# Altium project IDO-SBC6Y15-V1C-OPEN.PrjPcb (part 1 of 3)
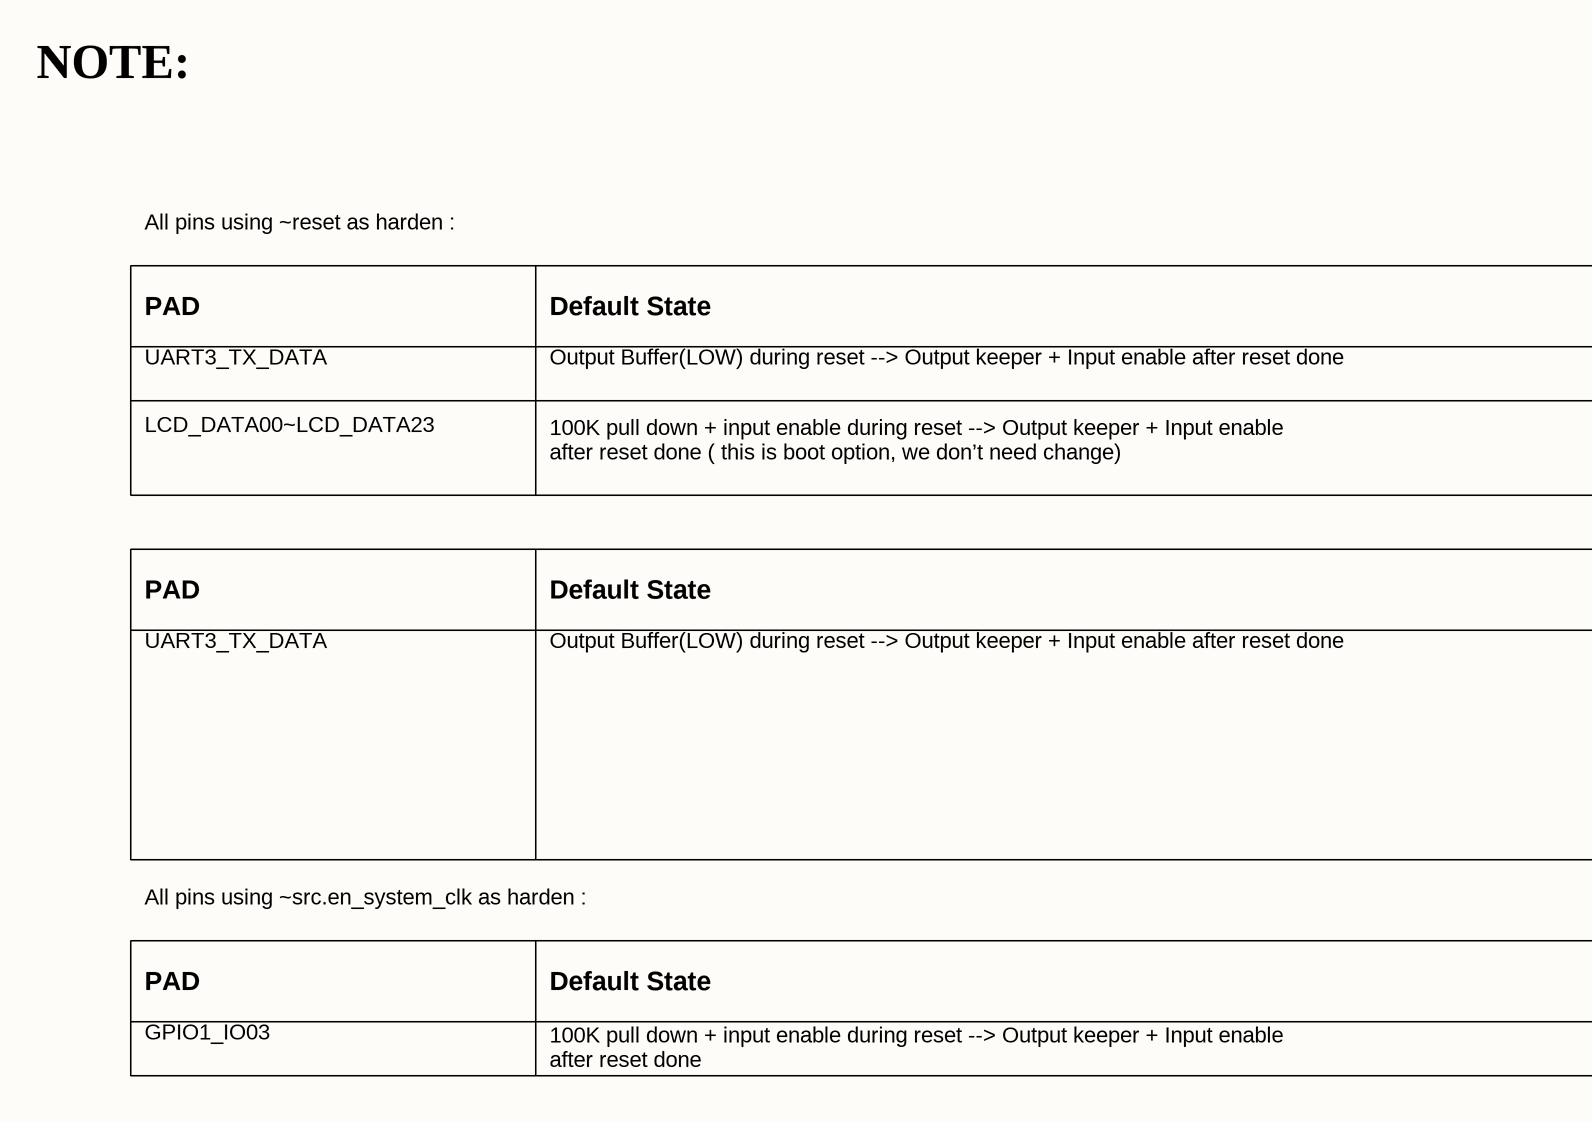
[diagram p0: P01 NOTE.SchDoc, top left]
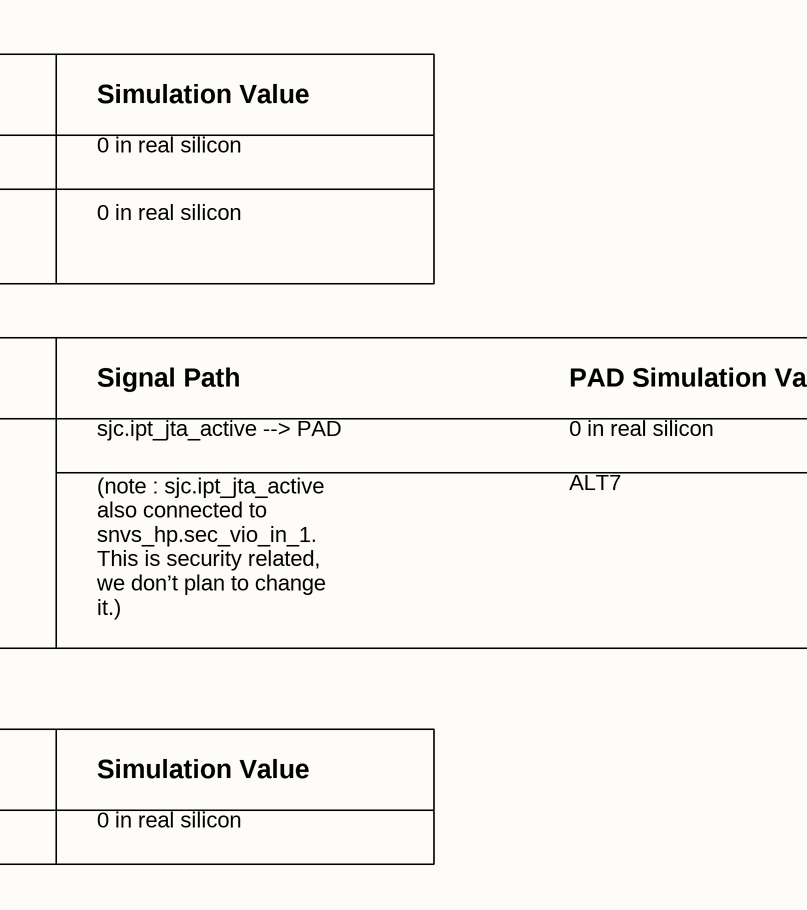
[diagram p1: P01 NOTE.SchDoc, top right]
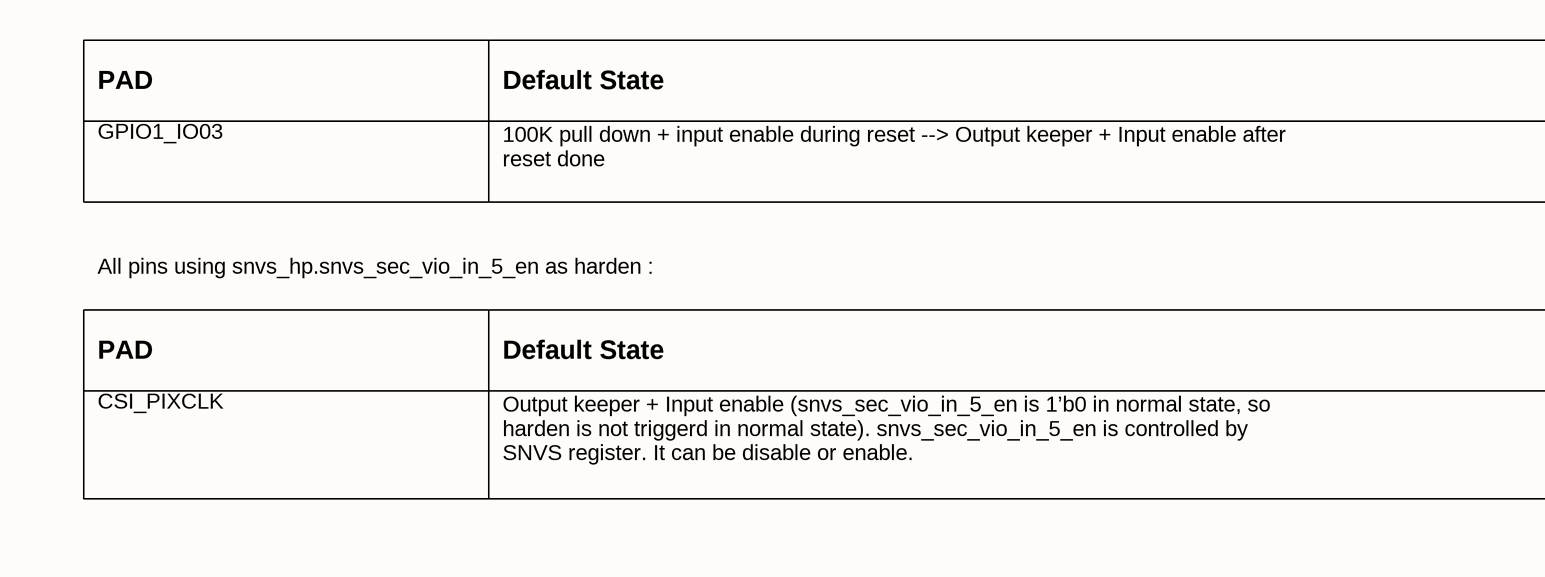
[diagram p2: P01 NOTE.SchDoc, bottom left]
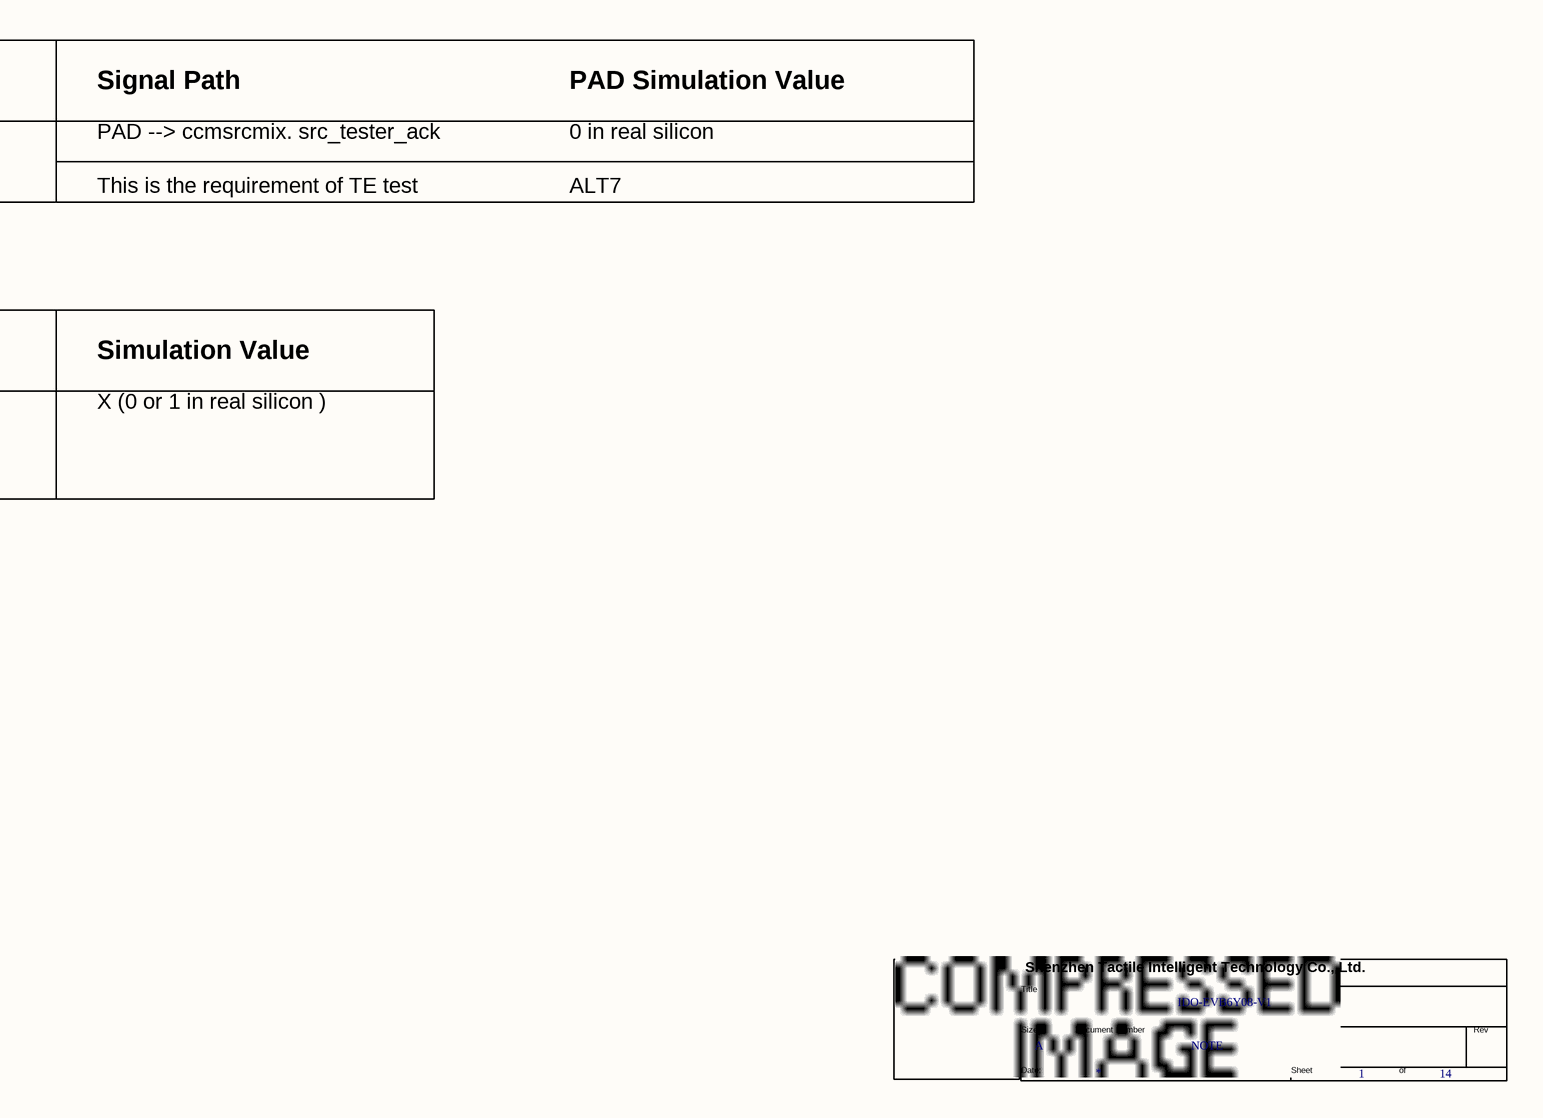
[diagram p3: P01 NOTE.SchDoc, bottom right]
12 sheets, 461 parts. Net scope: global (net labels, ports and power ports of the same name join across sheets).
Sheets:
  P01 NOTE.SchDoc
  P02 IOMUX.SchDoc
  P03 POWER TREE.SchDoc
  P04 BLOCK.SchDoc
  P05 POWER_SUPPLY_LED.SchDoc
  P06 SOM6ULX.SchDoc
  P07 SD_RTC.SchDoc
  P08 USB.SchDoc
  P09 ETHERNET.SchDoc
  P10 UART_Debug.SchDoc
  P12 EXPAND.SchDoc
  P11 4G_WIFI.SchDoc

## Sheet P01 NOTE.SchDoc
size 594 x 420 mm

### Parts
(Parts that share a designator on the sheet are numbered #1, #2 ... from top to bottom, then left to right.)
*#1  Doc: NOTE  Title: IDO-EVB6Y08-V1  Page Size: A  Page Number: 1  Page Count: 14  (hidden comment: TitleBlock1)  (graphical)

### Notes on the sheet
- NOTE:
- All pins using ~reset as harden :
- PAD
- Default State
- Simulation Value
- UART3_TX_DATA
- Output Buffer(LOW) during reset --> Output keeper + Input enable after reset done
- 0 in real silicon
- LCD_DATA00~LCD_DATA23
- 100K pull down + input enable during reset --> Output keeper + Input enable
  after reset done ( this is boot option, we don’t need change)
- sjc.ipt_jta_active --> PAD
- Signal Path
- PAD Simulation Value
- (note : sjc.ipt_jta_active
  also connected to
  snvs_hp.sec_vio_in_1.
  This is security related,
  we don’t plan to change
  it.)
- ALT7
- All pins using ~src.en_system_clk as harden :
- GPIO1_IO03
- 100K pull down + input enable during reset --> Output keeper + Input enable
  after reset done
- 100K pull down + input enable during reset --> Output keeper + Input enable after
  reset done
- PAD --> ccmsrcmix. src_tester_ack
- This is the requirement of TE test
- All pins using snvs_hp.snvs_sec_vio_in_5_en as harden :
- CSI_PIXCLK
- Output keeper + Input enable (snvs_sec_vio_in_5_en is 1’b0 in normal state, so
  harden is not triggerd in normal state). snvs_sec_vio_in_5_en is controlled by
  SNVS register. It can be disable or enable.
- X (0 or 1 in real silicon )

## Sheet P02 IOMUX.SchDoc
size 594 x 420 mm
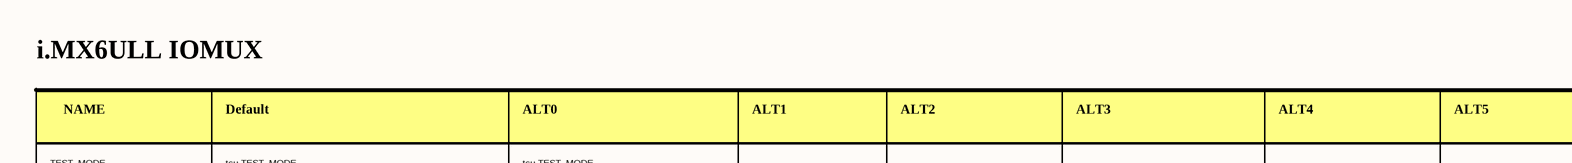
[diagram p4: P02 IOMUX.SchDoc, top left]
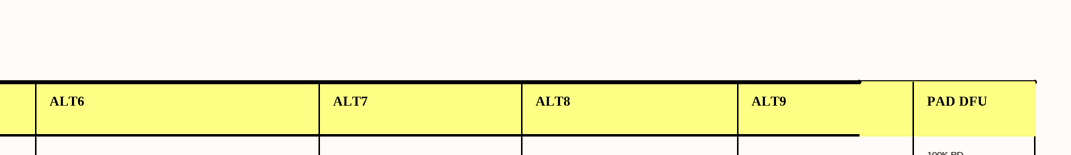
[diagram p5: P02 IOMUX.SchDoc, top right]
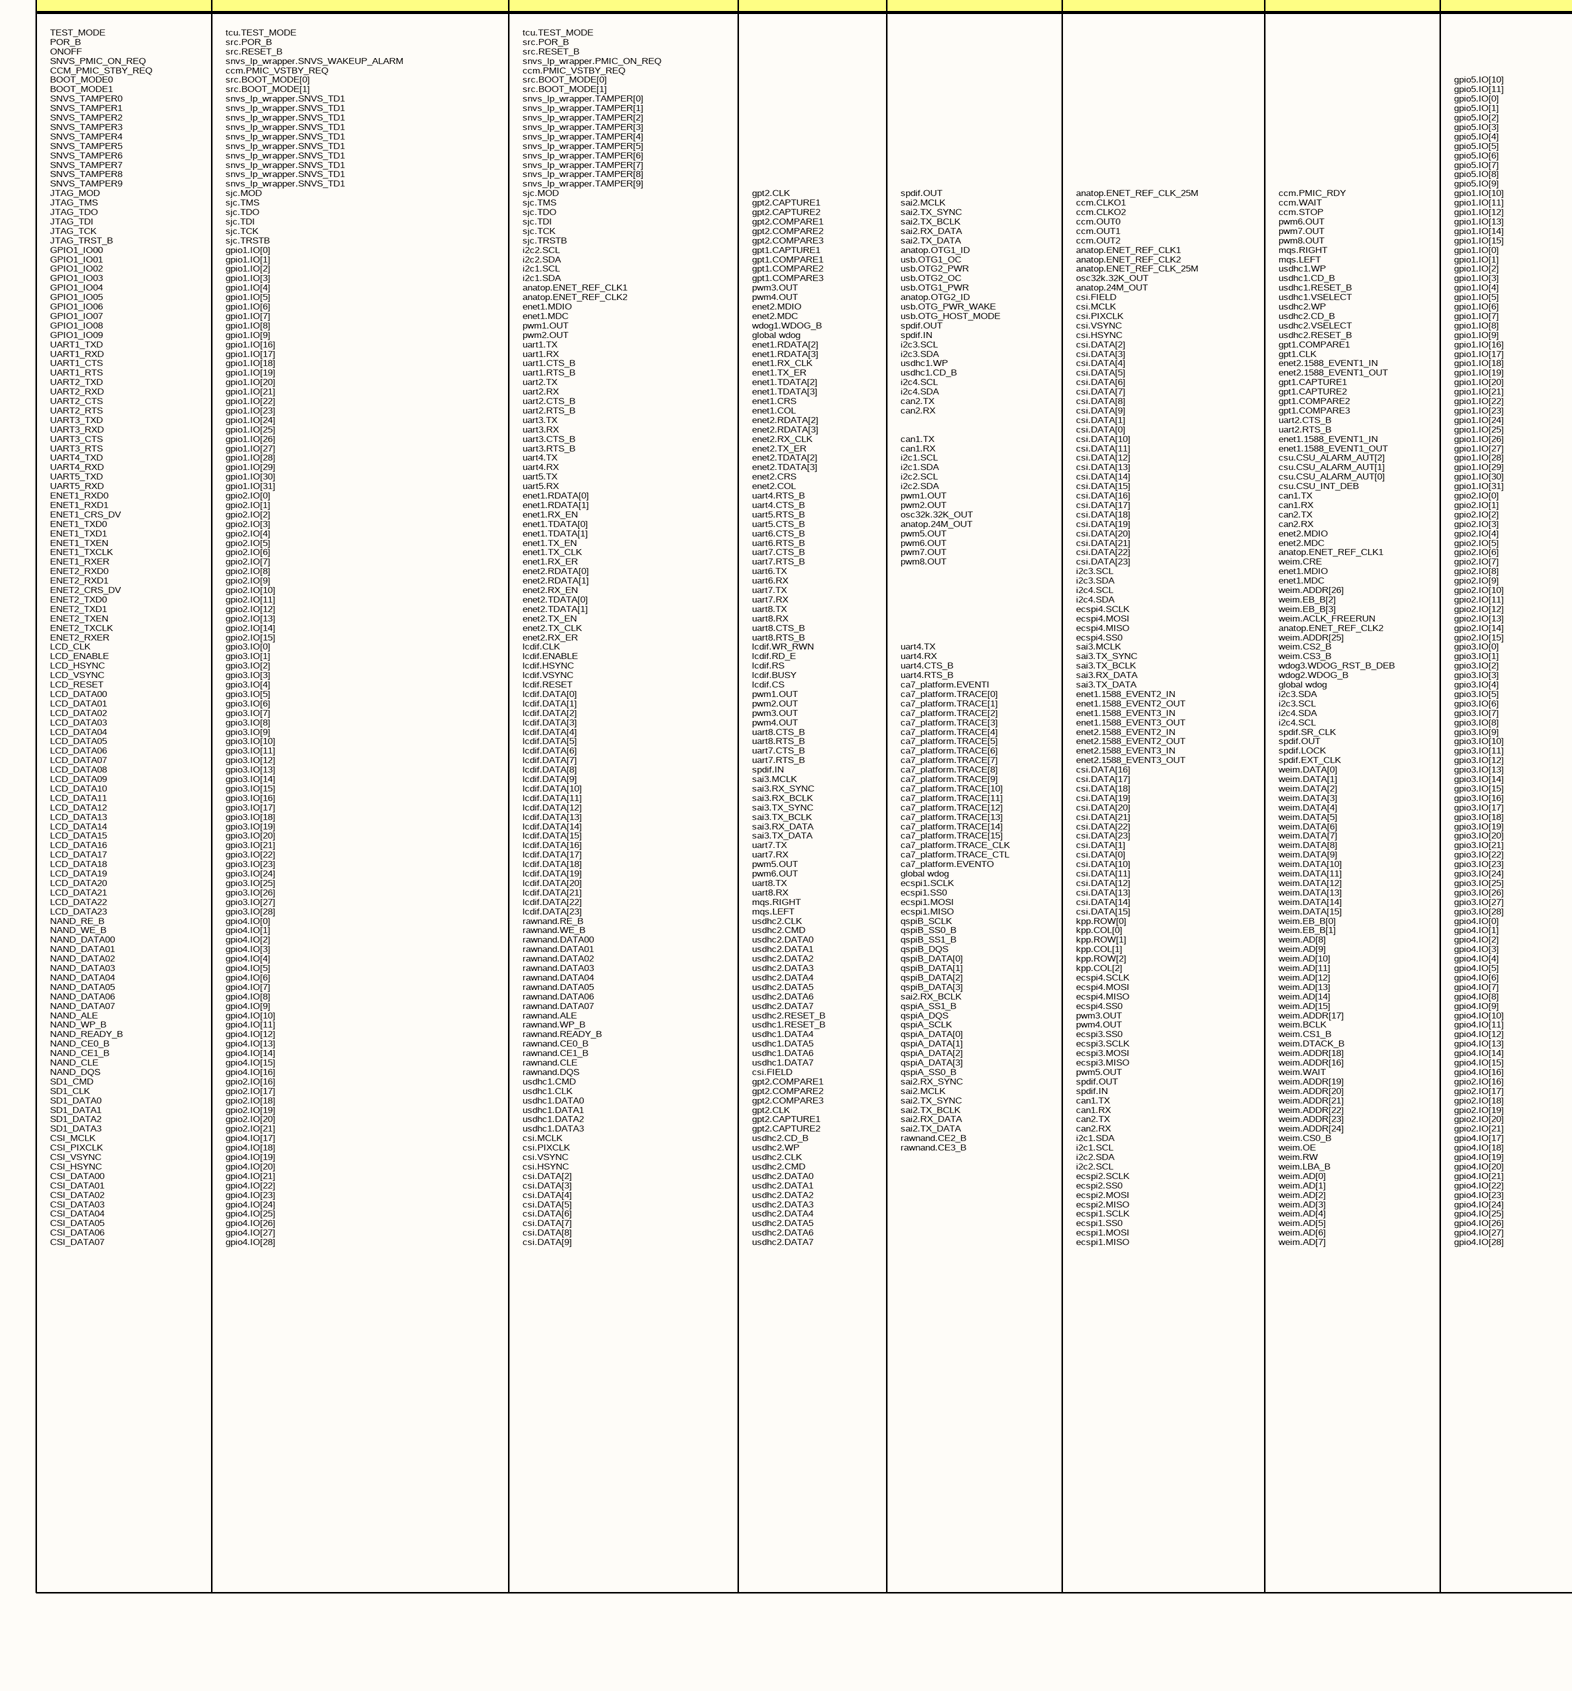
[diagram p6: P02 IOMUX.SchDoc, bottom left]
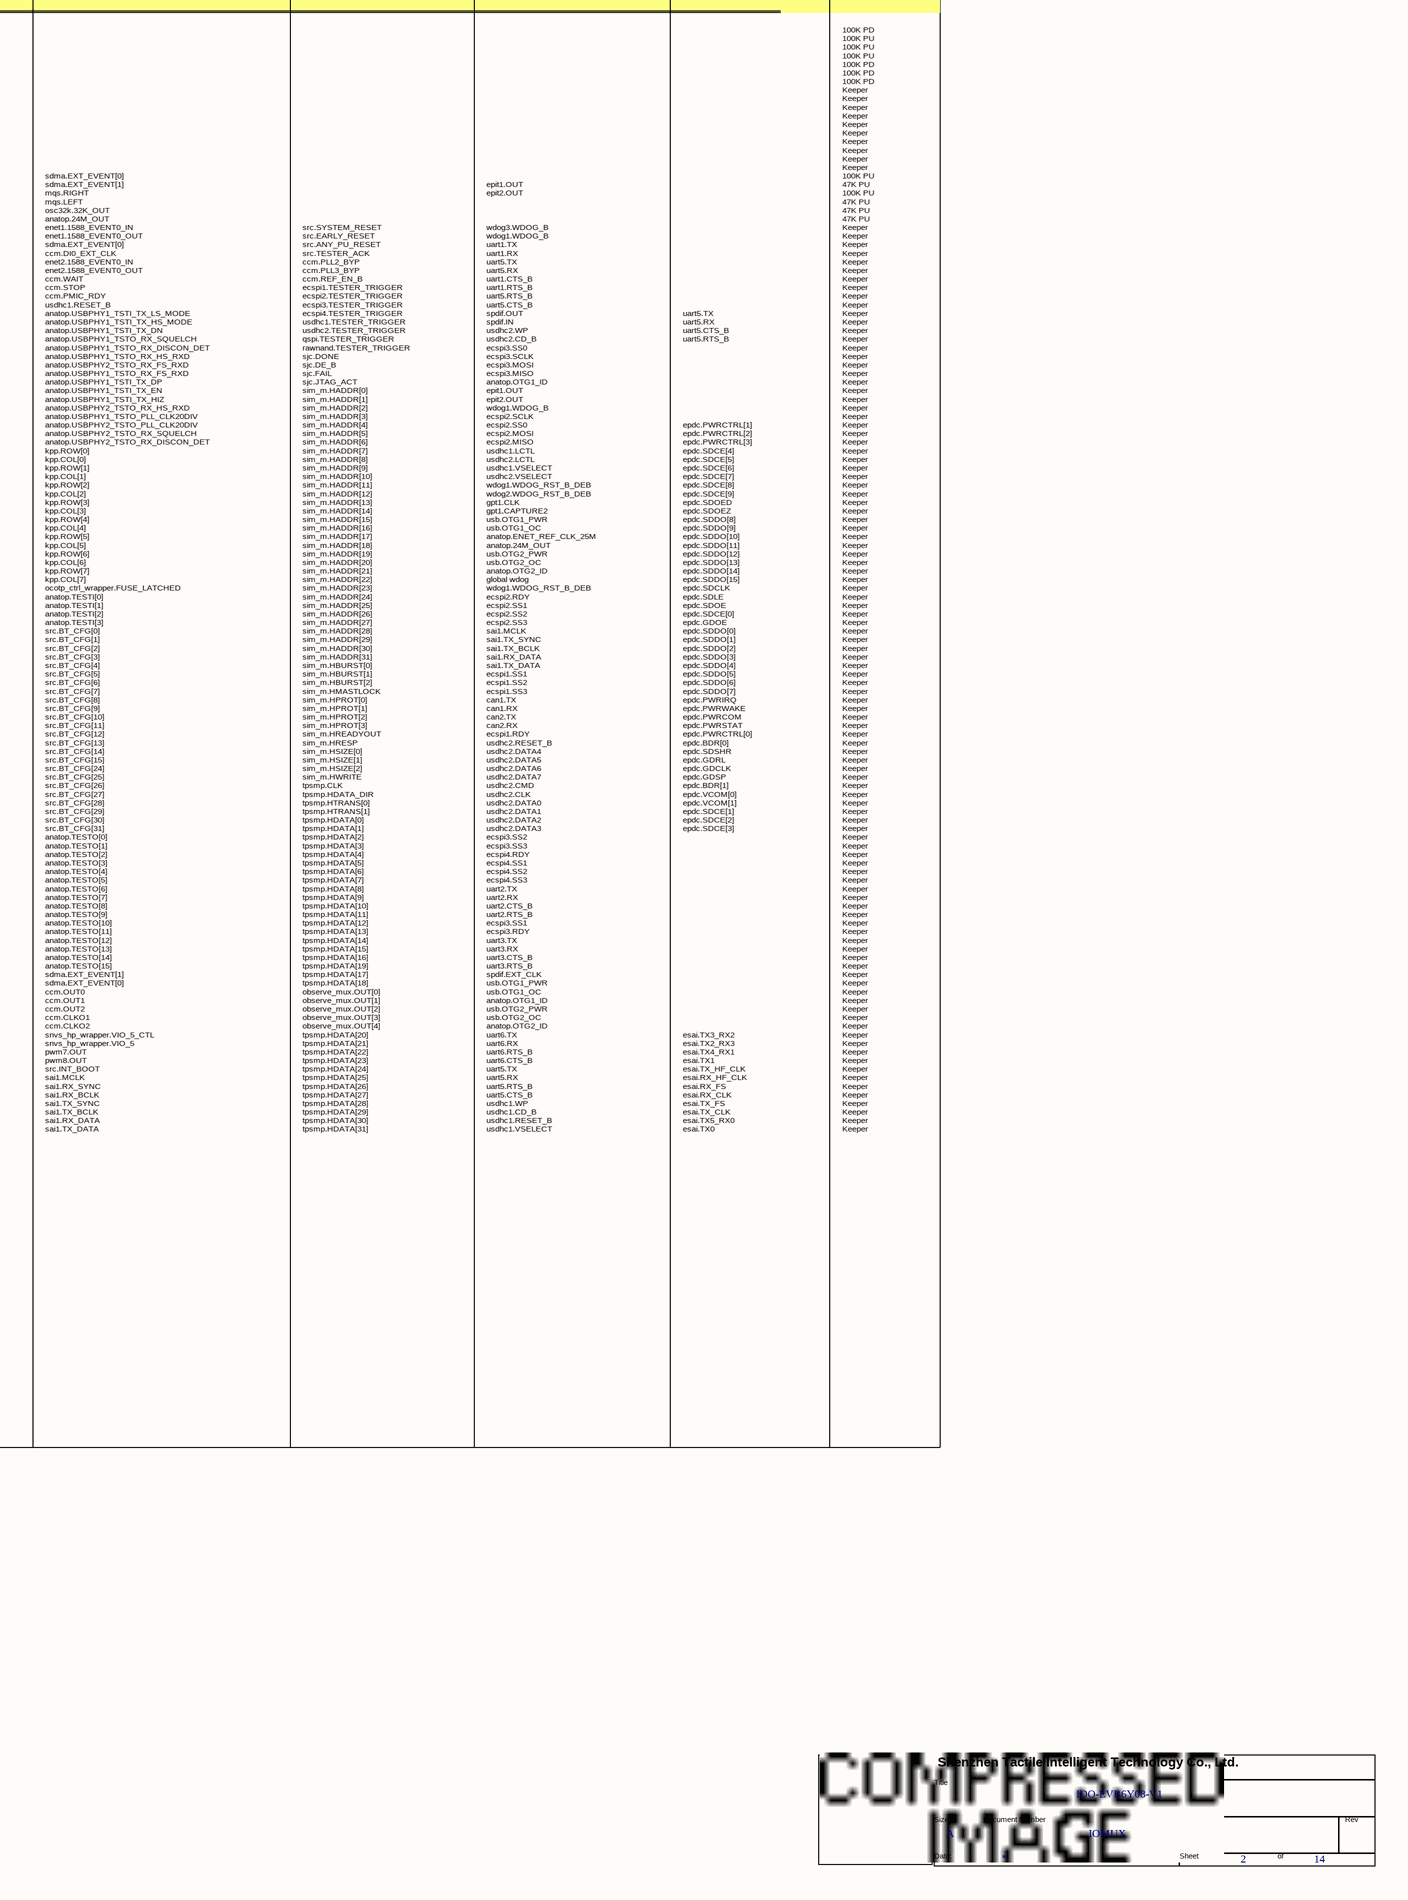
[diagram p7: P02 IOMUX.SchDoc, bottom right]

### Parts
(Parts that share a designator on the sheet are numbered #1, #2 ... from top to bottom, then left to right.)
*#2  Doc: IOMUX  Title: IDO-EVB6Y08-V1  Page Size: A  Page Number: 2  Page Count: 14  (hidden comment: TitleBlock1)  (graphical)

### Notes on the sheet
- i.MX6ULL IOMUX
- NAME
- Default
- ALT0
- ALT1
- ALT2
- ALT3
- ALT4
- ALT5
- ALT6
- ALT7
- ALT8
- ALT9
- PAD DFU
- TEST_MODE
  POR_B
  ONOFF
  SNVS_PMIC_ON_REQ
  CCM_PMIC_STBY_REQ
  BOOT_MODE0
  BOOT_MODE1
  SNVS_TAMPER0
  SNVS_TAMPER1
  SNVS_TAMPER2
  SNVS_TAMPER3
  SNVS_TAMPER4
  SNVS_TAMPER5
  SNVS_TAMPER6
  SNVS_TAMPER7
  SNVS_TAMPER8
  SNVS_TAMPER9
  JTAG_MOD
  JTAG_TMS
  JTAG_TDO
  JTAG_TDI
  JTAG_TCK
  JTAG_TRST_B
  GPIO1_IO00
  GPIO1_IO01
  GPIO1_IO02
  GPIO1_IO03
  GPIO1_IO04
  GPIO1_IO05
  GPIO1_IO06
  GPIO1_IO07
  GPIO1_IO08
  GPIO1_IO09
  UART1_TXD
  UART1_RXD
  UART1_CTS
  UART1_RTS
  UART2_TXD
  UART2_RXD
  UART2_CTS
  UART2_RTS
  UART3_TXD
  UART3_RXD
  UART3_CTS
  UART3_RTS
  UART4_TXD
  UART4_RXD
  UART5_TXD
  UART5_RXD
  ENET1_RXD0
  ENET1_RXD1
  ENET1_CRS_DV
  ENET1_TXD0
  ENET1_TXD1
  ENET1_TXEN
  ENET1_TXCLK
  ENET1_RXER
  ENET2_RXD0
  ENET2_RXD1
  ENET2_CRS_DV
  ENET2_TXD0
  ENET2_TXD1
  ENET2_TXEN
  ENET2_TXCLK
  ENET2_RXER
  LCD_CLK
  LCD_ENABLE
  LCD_HSYNC
  LCD_VSYNC
  LCD_RESET
  LCD_DATA00
  LCD_DATA01
  LCD_DATA02
  LCD_DATA03
  LCD_DATA04
  LCD_DATA05
  LCD_DATA06
  LCD_DATA07
  LCD_DATA08
  LCD_DATA09
  LCD_DATA10
  LCD_DATA11
  LCD_DATA12
  LCD_DATA13
  LCD_DATA14
  LCD_DATA15
  LCD_DATA16
  LCD_DATA17
  LCD_DATA18
  LCD_DATA19
  LCD_DATA20
  LCD_DATA21
  LCD_DATA22
  LCD_DATA23
  NAND_RE_B
  NAND_WE_B
  NAND_DATA00
  NAND_DATA01
  NAND_DATA02
  NAND_DATA03
  NAND_DATA04
  NAND_DATA05
  NAND_DATA06
  NAND_DATA07
  NAND_ALE
  NAND_WP_B
  NAND_READY_B
  NAND_CE0_B
  NAND_CE1_B
  NAND_CLE
  NAND_DQS
  SD1_CMD
  SD1_CLK
  SD1_DATA0
  SD1_DATA1
  SD1_DATA2
  SD1_DATA3
  CSI_MCLK
  CSI_PIXCLK
  CSI_VSYNC
  CSI_HSYNC
  CSI_DATA00
  CSI_DATA01
  CSI_DATA02
  CSI_DATA03
  CSI_DATA04
  CSI_DATA05
  CSI_DATA06
  CSI_DATA07
- tcu.TEST_MODE
  src.POR_B
  src.RESET_B
  snvs_lp_wrapper.SNVS_WAKEUP_ALARM
  ccm.PMIC_VSTBY_REQ
  src.BOOT_MODE[0]
  src.BOOT_MODE[1]
  snvs_lp_wrapper.SNVS_TD1
  snvs_lp_wrapper.SNVS_TD1
  snvs_lp_wrapper.SNVS_TD1
  snvs_lp_wrapper.SNVS_TD1
  snvs_lp_wrapper.SNVS_TD1
  snvs_lp_wrapper.SNVS_TD1
  snvs_lp_wrapper.SNVS_TD1
  snvs_lp_wrapper.SNVS_TD1
  snvs_lp_wrapper.SNVS_TD1
  snvs_lp_wrapper.SNVS_TD1
  sjc.MOD
  sjc.TMS
  sjc.TDO
  sjc.TDI
  sjc.TCK
  sjc.TRSTB
  gpio1.IO[0]
  gpio1.IO[1]
  gpio1.IO[2]
  gpio1.IO[3]
  gpio1.IO[4]
  gpio1.IO[5]
  gpio1.IO[6]
  gpio1.IO[7]
  gpio1.IO[8]
  gpio1.IO[9]
  gpio1.IO[16]
  gpio1.IO[17]
  gpio1.IO[18]
  gpio1.IO[19]
  gpio1.IO[20]
  gpio1.IO[21]
  gpio1.IO[22]
  gpio1.IO[23]
  gpio1.IO[24]
  gpio1.IO[25]
  gpio1.IO[26]
  gpio1.IO[27]
  gpio1.IO[28]
  gpio1.IO[29]
  gpio1.IO[30]
  gpio1.IO[31]
  gpio2.IO[0]
  gpio2.IO[1]
  gpio2.IO[2]
  gpio2.IO[3]
  gpio2.IO[4]
  gpio2.IO[5]
  gpio2.IO[6]
  gpio2.IO[7]
  gpio2.IO[8]
  gpio2.IO[9]
  gpio2.IO[10]
  gpio2.IO[11]
  gpio2.IO[12]
  gpio2.IO[13]
  gpio2.IO[14]
  gpio2.IO[15]
  gpio3.IO[0]
  gpio3.IO[1]
  gpio3.IO[2]
  gpio3.IO[3]
  gpio3.IO[4]
  gpio3.IO[5]
  gpio3.IO[6]
  gpio3.IO[7]
  gpio3.IO[8]
  gpio3.IO[9]
  gpio3.IO[10]
  gpio3.IO[11]
  gpio3.IO[12]
  gpio3.IO[13]
  gpio3.IO[14]
  gpio3.IO[15]
  gpio3.IO[16]
  gpio3.IO[17]
  gpio3.IO[18]
  gpio3.IO[19]
  gpio3.IO[20]
  gpio3.IO[21]
  gpio3.IO[22]
  gpio3.IO[23]
  gpio3.IO[24]
  gpio3.IO[25]
  gpio3.IO[26]
  gpio3.IO[27]
  gpio3.IO[28]
  gpio4.IO[0]
  gpio4.IO[1]
  gpio4.IO[2]
  gpio4.IO[3]
  gpio4.IO[4]
  gpio4.IO[5]
  gpio4.IO[6]
  gpio4.IO[7]
  gpio4.IO[8]
  gpio4.IO[9]
  gpio4.IO[10]
  gpio4.IO[11]
  gpio4.IO[12]
  gpio4.IO[13]
  gpio4.IO[14]
  gpio4.IO[15]
  gpio4.IO[16]
  gpio2.IO[16]
  gpio2.IO[17]
  gpio2.IO[18]
  gpio2.IO[19]
  gpio2.IO[20]
  gpio2.IO[21]
  gpio4.IO[17]
  gpio4.IO[18]
  gpio4.IO[19]
  gpio4.IO[20]
  gpio4.IO[21]
  gpio4.IO[22]
  gpio4.IO[23]
  gpio4.IO[24]
  gpio4.IO[25]
  gpio4.IO[26]
  gpio4.IO[27]
  gpio4.IO[28]
- tcu.TEST_MODE
  src.POR_B
  src.RESET_B
  snvs_lp_wrapper.PMIC_ON_REQ
  ccm.PMIC_VSTBY_REQ
  src.BOOT_MODE[0]
  src.BOOT_MODE[1]
  snvs_lp_wrapper.TAMPER[0]
  snvs_lp_wrapper.TAMPER[1]
  snvs_lp_wrapper.TAMPER[2]
  snvs_lp_wrapper.TAMPER[3]
  snvs_lp_wrapper.TAMPER[4]
  snvs_lp_wrapper.TAMPER[5]
  snvs_lp_wrapper.TAMPER[6]
  snvs_lp_wrapper.TAMPER[7]
  snvs_lp_wrapper.TAMPER[8]
  snvs_lp_wrapper.TAMPER[9]
  sjc.MOD
  sjc.TMS
  sjc.TDO
  sjc.TDI
  sjc.TCK
  sjc.TRSTB
  i2c2.SCL
  i2c2.SDA
  i2c1.SCL
  i2c1.SDA
  anatop.ENET_REF_CLK1
  anatop.ENET_REF_CLK2
  enet1.MDIO
  enet1.MDC
  pwm1.OUT
  pwm2.OUT
  uart1.TX
  uart1.RX
  uart1.CTS_B
  uart1.RTS_B
  uart2.TX
  uart2.RX
  uart2.CTS_B
  uart2.RTS_B
  uart3.TX
  uart3.RX
  uart3.CTS_B
  uart3.RTS_B
  uart4.TX
  uart4.RX
  uart5.TX
  uart5.RX
  enet1.RDATA[0]
  enet1.RDATA[1]
  enet1.RX_EN
  enet1.TDATA[0]
  enet1.TDATA[1]
  enet1.TX_EN
  enet1.TX_CLK
  enet1.RX_ER
  enet2.RDATA[0]
  enet2.RDATA[1]
  enet2.RX_EN
  enet2.TDATA[0]
  enet2.TDATA[1]
  enet2.TX_EN
  enet2.TX_CLK
  enet2.RX_ER
  lcdif.CLK
  lcdif.ENABLE
  lcdif.HSYNC
  lcdif.VSYNC
  lcdif.RESET
  lcdif.DATA[0]
  lcdif.DATA[1]
  lcdif.DATA[2]
  lcdif.DATA[3]
  lcdif.DATA[4]
  lcdif.DATA[5]
  lcdif.DATA[6]
  lcdif.DATA[7]
  lcdif.DATA[8]
  lcdif.DATA[9]
  lcdif.DATA[10]
  lcdif.DATA[11]
  lcdif.DATA[12]
  lcdif.DATA[13]
  lcdif.DATA[14]
  lcdif.DATA[15]
  lcdif.DATA[16]
  lcdif.DATA[17]
  lcdif.DATA[18]
  lcdif.DATA[19]
  lcdif.DATA[20]
  lcdif.DATA[21]
  lcdif.DATA[22]
  lcdif.DATA[23]
  rawnand.RE_B
  rawnand.WE_B
  rawnand.DATA00
  rawnand.DATA01
  rawnand.DATA02
  rawnand.DATA03
  rawnand.DATA04
  rawnand.DATA05
  rawnand.DATA06
  rawnand.DATA07
  rawnand.ALE
  rawnand.WP_B
  rawnand.READY_B
  rawnand.CE0_B
  rawnand.CE1_B
  rawnand.CLE
  rawnand.DQS
  usdhc1.CMD
  usdhc1.CLK
  usdhc1.DATA0
  usdhc1.DATA1
  usdhc1.DATA2
  usdhc1.DATA3
  csi.MCLK
  csi.PIXCLK
  csi.VSYNC
  csi.HSYNC
  csi.DATA[2]
  csi.DATA[3]
  csi.DATA[4]
  csi.DATA[5]
  csi.DATA[6]
  csi.DATA[7]
  csi.DATA[8]
  csi.DATA[9]
- gpt2.CLK
  gpt2.CAPTURE1
  gpt2.CAPTURE2
  gpt2.COMPARE1
  gpt2.COMPARE2
  gpt2.COMPARE3
  gpt1.CAPTURE1
  gpt1.COMPARE1
  gpt1.COMPARE2
  gpt1.COMPARE3
  pwm3.OUT
  pwm4.OUT
  enet2.MDIO
  enet2.MDC
  wdog1.WDOG_B
  global wdog
  enet1.RDATA[2]
  enet1.RDATA[3]
  enet1.RX_CLK
  enet1.TX_ER
  enet1.TDATA[2]
  enet1.TDATA[3]
  enet1.CRS
  enet1.COL
  enet2.RDATA[2]
  enet2.RDATA[3]
  enet2.RX_CLK
  enet2.TX_ER
  enet2.TDATA[2]
  enet2.TDATA[3]
  enet2.CRS
  enet2.COL
  uart4.RTS_B
  uart4.CTS_B
  uart5.RTS_B
  uart5.CTS_B
  uart6.CTS_B
  uart6.RTS_B
  uart7.CTS_B
  uart7.RTS_B
  uart6.TX
  uart6.RX
  uart7.TX
  uart7.RX
  uart8.TX
  uart8.RX
  uart8.CTS_B
  uart8.RTS_B
  lcdif.WR_RWN
  lcdif.RD_E
  lcdif.RS
  lcdif.BUSY
  lcdif.CS
  pwm1.OUT
  pwm2.OUT
  pwm3.OUT
  pwm4.OUT
  uart8.CTS_B
  uart8.RTS_B
  uart7.CTS_B
  uart7.RTS_B
  spdif.IN
  sai3.MCLK
  sai3.RX_SYNC
  sai3.RX_BCLK
  sai3.TX_SYNC
  sai3.TX_BCLK
  sai3.RX_DATA
  sai3.TX_DATA
  uart7.TX
  uart7.RX
  pwm5.OUT
  pwm6.OUT
  uart8.TX
  uart8.RX
  mqs.RIGHT
  mqs.LEFT
  usdhc2.CLK
  usdhc2.CMD
  usdhc2.DATA0
  usdhc2.DATA1
  usdhc2.DATA2
  usdhc2.DATA3
  usdhc2.DATA4
  usdhc2.DATA5
  usdhc2.DATA6
  usdhc2.DATA7
  usdhc2.RESET_B
  usdhc1.RESET_B
  usdhc1.DATA4
  usdhc1.DATA5
  usdhc1.DATA6
  usdhc1.DATA7
  csi.FIELD
  gpt2.COMPARE1
  gpt2.COMPARE2
  gpt2.COMPARE3
  gpt2.CLK
  gpt2.CAPTURE1
  gpt2.CAPTURE2
  usdhc2.CD_B
  usdhc2.WP
  usdhc2.CLK
  usdhc2.CMD
  usdhc2.DATA0
  usdhc2.DATA1
  usdhc2.DATA2
  usdhc2.DATA3
  usdhc2.DATA4
  usdhc2.DATA5
  usdhc2.DATA6
  usdhc2.DATA7
- spdif.OUT
  sai2.MCLK
  sai2.TX_SYNC
  sai2.TX_BCLK
  sai2.RX_DATA
  sai2.TX_DATA
  anatop.OTG1_ID
  usb.OTG1_OC
  usb.OTG2_PWR
  usb.OTG2_OC
  usb.OTG1_PWR
  anatop.OTG2_ID
  usb.OTG_PWR_WAKE
  usb.OTG_HOST_MODE
  spdif.OUT
  spdif.IN
  i2c3.SCL
  i2c3.SDA
  usdhc1.WP
  usdhc1.CD_B
  i2c4.SCL
  i2c4.SDA
  can2.TX
  can2.RX
  can1.TX
  can1.RX
  i2c1.SCL
  i2c1.SDA
  i2c2.SCL
  i2c2.SDA
  pwm1.OUT
  pwm2.OUT
  osc32k.32K_OUT
  anatop.24M_OUT
  pwm5.OUT
  pwm6.OUT
  pwm7.OUT
  pwm8.OUT
  uart4.TX
  uart4.RX
  uart4.CTS_B
  uart4.RTS_B
  ca7_platform.EVENTI
  ca7_platform.TRACE[0]
  ca7_platform.TRACE[1]
  ca7_platform.TRACE[2]
  ca7_platform.TRACE[3]
  ca7_platform.TRACE[4]
  ca7_platform.TRACE[5]
  ca7_platform.TRACE[6]
  ca7_platform.TRACE[7]
  ca7_platform.TRACE[8]
  ca7_platform.TRACE[9]
  ca7_platform.TRACE[10]
  ca7_platform.TRACE[11]
  ca7_platform.TRACE[12]
  ca7_platform.TRACE[13]
  ca7_platform.TRACE[14]
  ca7_platform.TRACE[15]
  ca7_platform.TRACE_CLK
  ca7_platform.TRACE_CTL
  ca7_platform.EVENTO
  global wdog
  ecspi1.SCLK
  ecspi1.SS0
  ecspi1.MOSI
  ecspi1.MISO
  qspiB_SCLK
  qspiB_SS0_B
  qspiB_SS1_B
  qspiB_DQS
  qspiB_DATA[0]
  qspiB_DATA[1]
  qspiB_DATA[2]
  qspiB_DATA[3]
  sai2.RX_BCLK
  qspiA_SS1_B
  qspiA_DQS
  qspiA_SCLK
  qspiA_DATA[0]
  qspiA_DATA[1]
  qspiA_DATA[2]
  qspiA_DATA[3]
  qspiA_SS0_B
  sai2.RX_SYNC
  sai2.MCLK
  sai2.TX_SYNC
  sai2.TX_BCLK
  sai2.RX_DATA
  sai2.TX_DATA
  rawnand.CE2_B
  rawnand.CE3_B
- anatop.ENET_REF_CLK_25M
  ccm.CLKO1
  ccm.CLKO2
  ccm.OUT0
  ccm.OUT1
  ccm.OUT2
  anatop.ENET_REF_CLK1
  anatop.ENET_REF_CLK2
  anatop.ENET_REF_CLK_25M
  osc32k.32K_OUT
  anatop.24M_OUT
  csi.FIELD
  csi.MCLK
  csi.PIXCLK
  csi.VSYNC
  csi.HSYNC
  csi.DATA[2]
  csi.DATA[3]
  csi.DATA[4]
  csi.DATA[5]
  csi.DATA[6]
  csi.DATA[7]
  csi.DATA[8]
  csi.DATA[9]
  csi.DATA[1]
  csi.DATA[0]
  csi.DATA[10]
  csi.DATA[11]
  csi.DATA[12]
  csi.DATA[13]
  csi.DATA[14]
  csi.DATA[15]
  csi.DATA[16]
  csi.DATA[17]
  csi.DATA[18]
  csi.DATA[19]
  csi.DATA[20]
  csi.DATA[21]
  csi.DATA[22]
  csi.DATA[23]
  i2c3.SCL
  i2c3.SDA
  i2c4.SCL
  i2c4.SDA
  ecspi4.SCLK
  ecspi4.MOSI
  ecspi4.MISO
  ecspi4.SS0
  sai3.MCLK
  sai3.TX_SYNC
  sai3.TX_BCLK
  sai3.RX_DATA
  sai3.TX_DATA
  enet1.1588_EVENT2_IN
  enet1.1588_EVENT2_OUT
  enet1.1588_EVENT3_IN
  enet1.1588_EVENT3_OUT
  enet2.1588_EVENT2_IN
  enet2.1588_EVENT2_OUT
  enet2.1588_EVENT3_IN
  enet2.1588_EVENT3_OUT
  csi.DATA[16]
  csi.DATA[17]
  csi.DATA[18]
  csi.DATA[19]
  csi.DATA[20]
  csi.DATA[21]
  csi.DATA[22]
  csi.DATA[23]
  csi.DATA[1]
  csi.DATA[0]
  csi.DATA[10]
  csi.DATA[11]
  csi.DATA[12]
  csi.DATA[13]
  csi.DATA[14]
  csi.DATA[15]
  kpp.ROW[0]
  kpp.COL[0]
  kpp.ROW[1]
  kpp.COL[1]
  kpp.ROW[2]
  kpp.COL[2]
  ecspi4.SCLK
  ecspi4.MOSI
  ecspi4.MISO
  ecspi4.SS0
  pwm3.OUT
  pwm4.OUT
  ecspi3.SS0
  ecspi3.SCLK
  ecspi3.MOSI
  ecspi3.MISO
  pwm5.OUT
  spdif.OUT
  spdif.IN
  can1.TX
  can1.RX
  can2.TX
  can2.RX
  i2c1.SDA
  i2c1.SCL
  i2c2.SDA
  i2c2.SCL
  ecspi2.SCLK
  ecspi2.SS0
  ecspi2.MOSI
  ecspi2.MISO
  ecspi1.SCLK
  ecspi1.SS0
  ecspi1.MOSI
  ecspi1.MISO
- ccm.PMIC_RDY
  ccm.WAIT
  ccm.STOP
  pwm6.OUT
  pwm7.OUT
  pwm8.OUT
  mqs.RIGHT
  mqs.LEFT
  usdhc1.WP
  usdhc1.CD_B
  usdhc1.RESET_B
  usdhc1.VSELECT
  usdhc2.WP
  usdhc2.CD_B
  usdhc2.VSELECT
  usdhc2.RESET_B
  gpt1.COMPARE1
  gpt1.CLK
  enet2.1588_EVENT1_IN
  enet2.1588_EVENT1_OUT
  gpt1.CAPTURE1
  gpt1.CAPTURE2
  gpt1.COMPARE2
  gpt1.COMPARE3
  uart2.CTS_B
  uart2.RTS_B
  enet1.1588_EVENT1_IN
  enet1.1588_EVENT1_OUT
  csu.CSU_ALARM_AUT[2]
  csu.CSU_ALARM_AUT[1]
  csu.CSU_ALARM_AUT[0]
  csu.CSU_INT_DEB
  can1.TX
  can1.RX
  can2.TX
  can2.RX
  enet2.MDIO
  enet2.MDC
  anatop.ENET_REF_CLK1
  weim.CRE
  enet1.MDIO
  enet1.MDC
  weim.ADDR[26]
  weim.EB_B[2]
  weim.EB_B[3]
  weim.ACLK_FREERUN
  anatop.ENET_REF_CLK2
  weim.ADDR[25]
  weim.CS2_B
  weim.CS3_B
  wdog3.WDOG_RST_B_DEB
  wdog2.WDOG_B
  global wdog
  i2c3.SDA
  i2c3.SCL
  i2c4.SDA
  i2c4.SCL
  spdif.SR_CLK
  spdif.OUT
  spdif.LOCK
  spdif.EXT_CLK
  weim.DATA[0]
  weim.DATA[1]
  weim.DATA[2]
  weim.DATA[3]
  weim.DATA[4]
  weim.DATA[5]
  weim.DATA[6]
  weim.DATA[7]
  weim.DATA[8]
  weim.DATA[9]
  weim.DATA[10]
  weim.DATA[11]
  weim.DATA[12]
  weim.DATA[13]
  weim.DATA[14]
  weim.DATA[15]
  weim.EB_B[0]
  weim.EB_B[1]
  weim.AD[8]
  weim.AD[9]
  weim.AD[10]
  weim.AD[11]
  weim.AD[12]
  weim.AD[13]
  weim.AD[14]
  weim.AD[15]
  weim.ADDR[17]
  weim.BCLK
  weim.CS1_B
  weim.DTACK_B
  weim.ADDR[18]
  weim.ADDR[16]
  weim.WAIT
  weim.ADDR[19]
  weim.ADDR[20]
  weim.ADDR[21]
  weim.ADDR[22]
  weim.ADDR[23]
  weim.ADDR[24]
  weim.CS0_B
  weim.OE
  weim.RW
  weim.LBA_B
  weim.AD[0]
  weim.AD[1]
  weim.AD[2]
  weim.AD[3]
  weim.AD[4]
  weim.AD[5]
  weim.AD[6]
  weim.AD[7]
- gpio5.IO[10]
  gpio5.IO[11]
  gpio5.IO[0]
  gpio5.IO[1]
  gpio5.IO[2]
  gpio5.IO[3]
  gpio5.IO[4]
  gpio5.IO[5]
  gpio5.IO[6]
  gpio5.IO[7]
  gpio5.IO[8]
  gpio5.IO[9]
  gpio1.IO[10]
  gpio1.IO[11]
  gpio1.IO[12]
  gpio1.IO[13]
  gpio1.IO[14]
  gpio1.IO[15]
  gpio1.IO[0]
  gpio1.IO[1]
  gpio1.IO[2]
  gpio1.IO[3]
  gpio1.IO[4]
  gpio1.IO[5]
  gpio1.IO[6]
  gpio1.IO[7]
  gpio1.IO[8]
  gpio1.IO[9]
  gpio1.IO[16]
  gpio1.IO[17]
  gpio1.IO[18]
  gpio1.IO[19]
  gpio1.IO[20]
  gpio1.IO[21]
  gpio1.IO[22]
  gpio1.IO[23]
  gpio1.IO[24]
  gpio1.IO[25]
  gpio1.IO[26]
  gpio1.IO[27]
  gpio1.IO[28]
  gpio1.IO[29]
  gpio1.IO[30]
  gpio1.IO[31]
  gpio2.IO[0]
  gpio2.IO[1]
  gpio2.IO[2]
  gpio2.IO[3]
  gpio2.IO[4]
  gpio2.IO[5]
  gpio2.IO[6]
  gpio2.IO[7]
  gpio2.IO[8]
  gpio2.IO[9]
  gpio2.IO[10]
  gpio2.IO[11]
  gpio2.IO[12]
  gpio2.IO[13]
  gpio2.IO[14]
  gpio2.IO[15]
  gpio3.IO[0]
  gpio3.IO[1]
  gpio3.IO[2]
  gpio3.IO[3]
  gpio3.IO[4]
  gpio3.IO[5]
  gpio3.IO[6]
  gpio3.IO[7]
  gpio3.IO[8]
  gpio3.IO[9]
  gpio3.IO[10]
  gpio3.IO[11]
  gpio3.IO[12]
  gpio3.IO[13]
  gpio3.IO[14]
  gpio3.IO[15]
  gpio3.IO[16]
  gpio3.IO[17]
  gpio3.IO[18]
  gpio3.IO[19]
  gpio3.IO[20]
  gpio3.IO[21]
  gpio3.IO[22]
  gpio3.IO[23]
  gpio3.IO[24]
  gpio3.IO[25]
  gpio3.IO[26]
  gpio3.IO[27]
  gpio3.IO[28]
  gpio4.IO[0]
  gpio4.IO[1]
  gpio4.IO[2]
  gpio4.IO[3]
  gpio4.IO[4]
  gpio4.IO[5]
  gpio4.IO[6]
  gpio4.IO[7]
  gpio4.IO[8]
  gpio4.IO[9]
  gpio4.IO[10]
  gpio4.IO[11]
  gpio4.IO[12]
  gpio4.IO[13]
  gpio4.IO[14]
  gpio4.IO[15]
  gpio4.IO[16]
  gpio2.IO[16]
  gpio2.IO[17]
  gpio2.IO[18]
  gpio2.IO[19]
  gpio2.IO[20]
  gpio2.IO[21]
  gpio4.IO[17]
  gpio4.IO[18]
  gpio4.IO[19]
  gpio4.IO[20]
  gpio4.IO[21]
  gpio4.IO[22]
  gpio4.IO[23]
  gpio4.IO[24]
  gpio4.IO[25]
  gpio4.IO[26]
  gpio4.IO[27]
  gpio4.IO[28]
- sdma.EXT_EVENT[0]
  sdma.EXT_EVENT[1]
  mqs.RIGHT
  mqs.LEFT
  osc32k.32K_OUT
  anatop.24M_OUT
  enet1.1588_EVENT0_IN
  enet1.1588_EVENT0_OUT
  sdma.EXT_EVENT[0]
  ccm.DI0_EXT_CLK
  enet2.1588_EVENT0_IN
  enet2.1588_EVENT0_OUT
  ccm.WAIT
  ccm.STOP
  ccm.PMIC_RDY
  usdhc1.RESET_B
  anatop.USBPHY1_TSTI_TX_LS_MODE
  anatop.USBPHY1_TSTI_TX_HS_MODE
  anatop.USBPHY1_TSTI_TX_DN
  anatop.USBPHY1_TSTO_RX_SQUELCH
  anatop.USBPHY1_TSTO_RX_DISCON_DET
  anatop.USBPHY1_TSTO_RX_HS_RXD
  anatop.USBPHY2_TSTO_RX_FS_RXD
  anatop.USBPHY1_TSTO_RX_FS_RXD
  anatop.USBPHY1_TSTI_TX_DP
  anatop.USBPHY1_TSTI_TX_EN
  anatop.USBPHY1_TSTI_TX_HIZ
  anatop.USBPHY2_TSTO_RX_HS_RXD
  anatop.USBPHY1_TSTO_PLL_CLK20DIV
  anatop.USBPHY2_TSTO_PLL_CLK20DIV
  anatop.USBPHY2_TSTO_RX_SQUELCH
  anatop.USBPHY2_TSTO_RX_DISCON_DET
  kpp.ROW[0]
  kpp.COL[0]
  kpp.ROW[1]
  kpp.COL[1]
  kpp.ROW[2]
  kpp.COL[2]
  kpp.ROW[3]
  kpp.COL[3]
  kpp.ROW[4]
  kpp.COL[4]
  kpp.ROW[5]
  kpp.COL[5]
  kpp.ROW[6]
  kpp.COL[6]
  kpp.ROW[7]
  kpp.COL[7]
  ocotp_ctrl_wrapper.FUSE_LATCHED
  anatop.TESTI[0]
  anatop.TESTI[1]
  anatop.TESTI[2]
  anatop.TESTI[3]
  src.BT_CFG[0]
  src.BT_CFG[1]
  src.BT_CFG[2]
  src.BT_CFG[3]
  src.BT_CFG[4]
  src.BT_CFG[5]
  src.BT_CFG[6]
  src.BT_CFG[7]
  src.BT_CFG[8]
  src.BT_CFG[9]
  src.BT_CFG[10]
  src.BT_CFG[11]
  src.BT_CFG[12]
  src.BT_CFG[13]
  src.BT_CFG[14]
  src.BT_CFG[15]
  src.BT_CFG[24]
  src.BT_CFG[25]
  src.BT_CFG[26]
  src.BT_CFG[27]
  src.BT_CFG[28]
  src.BT_CFG[29]
  src.BT_CFG[30]
  src.BT_CFG[31]
  anatop.TESTO[0]
  anatop.TESTO[1]
  anatop.TESTO[2]
  anatop.TESTO[3]
  anatop.TESTO[4]
  anatop.TESTO[5]
  anatop.TESTO[6]
  anatop.TESTO[7]
  anatop.TESTO[8]
  anatop.TESTO[9]
  anatop.TESTO[10]
  anatop.TESTO[11]
  anatop.TESTO[12]
  anatop.TESTO[13]
  anatop.TESTO[14]
  anatop.TESTO[15]
  sdma.EXT_EVENT[1]
  sdma.EXT_EVENT[0]
  ccm.OUT0
  ccm.OUT1
  ccm.OUT2
  ccm.CLKO1
  ccm.CLKO2
  snvs_hp_wrapper.VIO_5_CTL
  snvs_hp_wrapper.VIO_5
  pwm7.OUT
  pwm8.OUT
  src.INT_BOOT
  sai1.MCLK
  sai1.RX_SYNC
  sai1.RX_BCLK
  sai1.TX_SYNC
  sai1.TX_BCLK
  sai1.RX_DATA
  sai1.TX_DATA
- src.SYSTEM_RESET
  src.EARLY_RESET
  src.ANY_PU_RESET
  src.TESTER_ACK
  ccm.PLL2_BYP
  ccm.PLL3_BYP
  ccm.REF_EN_B
  ecspi1.TESTER_TRIGGER
  ecspi2.TESTER_TRIGGER
  ecspi3.TESTER_TRIGGER
  ecspi4.TESTER_TRIGGER
  usdhc1.TESTER_TRIGGER
  usdhc2.TESTER_TRIGGER
  qspi.TESTER_TRIGGER
  rawnand.TESTER_TRIGGER
  sjc.DONE
  sjc.DE_B
  sjc.FAIL
  sjc.JTAG_ACT
  sim_m.HADDR[0]
  sim_m.HADDR[1]
  sim_m.HADDR[2]
  sim_m.HADDR[3]
  sim_m.HADDR[4]
  sim_m.HADDR[5]
  sim_m.HADDR[6]
  sim_m.HADDR[7]
  sim_m.HADDR[8]
  sim_m.HADDR[9]
  sim_m.HADDR[10]
  sim_m.HADDR[11]
  sim_m.HADDR[12]
  sim_m.HADDR[13]
  sim_m.HADDR[14]
  sim_m.HADDR[15]
  sim_m.HADDR[16]
  sim_m.HADDR[17]
  sim_m.HADDR[18]
  sim_m.HADDR[19]
  sim_m.HADDR[20]
  sim_m.HADDR[21]
  sim_m.HADDR[22]
  sim_m.HADDR[23]
  sim_m.HADDR[24]
  sim_m.HADDR[25]
  sim_m.HADDR[26]
  sim_m.HADDR[27]
  sim_m.HADDR[28]
  sim_m.HADDR[29]
  sim_m.HADDR[30]
  sim_m.HADDR[31]
  sim_m.HBURST[0]
  sim_m.HBURST[1]
  sim_m.HBURST[2]
  sim_m.HMASTLOCK
  sim_m.HPROT[0]
  sim_m.HPROT[1]
  sim_m.HPROT[2]
  sim_m.HPROT[3]
  sim_m.HREADYOUT
  sim_m.HRESP
  sim_m.HSIZE[0]
  sim_m.HSIZE[1]
  sim_m.HSIZE[2]
  sim_m.HWRITE
  tpsmp.CLK
  tpsmp.HDATA_DIR
  tpsmp.HTRANS[0]
  tpsmp.HTRANS[1]
  tpsmp.HDATA[0]
  tpsmp.HDATA[1]
  tpsmp.HDATA[2]
  tpsmp.HDATA[3]
  tpsmp.HDATA[4]
  tpsmp.HDATA[5]
  tpsmp.HDATA[6]
  tpsmp.HDATA[7]
  tpsmp.HDATA[8]
  tpsmp.HDATA[9]
  tpsmp.HDATA[10]
  tpsmp.HDATA[11]
  tpsmp.HDATA[12]
  tpsmp.HDATA[13]
  tpsmp.HDATA[14]
  tpsmp.HDATA[15]
  tpsmp.HDATA[16]
  tpsmp.HDATA[19]
  tpsmp.HDATA[17]
  tpsmp.HDATA[18]
  observe_mux.OUT[0]
  observe_mux.OUT[1]
  observe_mux.OUT[2]
  observe_mux.OUT[3]
  observe_mux.OUT[4]
  tpsmp.HDATA[20]
  tpsmp.HDATA[21]
  tpsmp.HDATA[22]
  tpsmp.HDATA[23]
  tpsmp.HDATA[24]
  tpsmp.HDATA[25]
  tpsmp.HDATA[26]
  tpsmp.HDATA[27]
  tpsmp.HDATA[28]
  tpsmp.HDATA[29]
  tpsmp.HDATA[30]
  tpsmp.HDATA[31]
- epit1.OUT
  epit2.OUT
  wdog3.WDOG_B
  wdog1.WDOG_B
  uart1.TX
  uart1.RX
  uart5.TX
  uart5.RX
  uart1.CTS_B
  uart1.RTS_B
  uart5.RTS_B
  uart5.CTS_B
  spdif.OUT
  spdif.IN
  usdhc2.WP
  usdhc2.CD_B
  ecspi3.SS0
  ecspi3.SCLK
  ecspi3.MOSI
  ecspi3.MISO
  anatop.OTG1_ID
  epit1.OUT
  epit2.OUT
  wdog1.WDOG_B
  ecspi2.SCLK
  ecspi2.SS0
  ecspi2.MOSI
  ecspi2.MISO
  usdhc1.LCTL
  usdhc2.LCTL
  usdhc1.VSELECT
  usdhc2.VSELECT
  wdog1.WDOG_RST_B_DEB
  wdog2.WDOG_RST_B_DEB
  gpt1.CLK
  gpt1.CAPTURE2
  usb.OTG1_PWR
  usb.OTG1_OC
  anatop.ENET_REF_CLK_25M
  anatop.24M_OUT
  usb.OTG2_PWR
  usb.OTG2_OC
  anatop.OTG2_ID
  global wdog
  wdog1.WDOG_RST_B_DEB
  ecspi2.RDY
  ecspi2.SS1
  ecspi2.SS2
  ecspi2.SS3
  sai1.MCLK
  sai1.TX_SYNC
  sai1.TX_BCLK
  sai1.RX_DATA
  sai1.TX_DATA
  ecspi1.SS1
  ecspi1.SS2
  ecspi1.SS3
  can1.TX
  can1.RX
  can2.TX
  can2.RX
  ecspi1.RDY
  usdhc2.RESET_B
  usdhc2.DATA4
  usdhc2.DATA5
  usdhc2.DATA6
  usdhc2.DATA7
  usdhc2.CMD
  usdhc2.CLK
  usdhc2.DATA0
  usdhc2.DATA1
  usdhc2.DATA2
  usdhc2.DATA3
  ecspi3.SS2
  ecspi3.SS3
  ecspi4.RDY
  ecspi4.SS1
  ecspi4.SS2
  ecspi4.SS3
  uart2.TX
  uart2.RX
  uart2.CTS_B
  uart2.RTS_B
  ecspi3.SS1
  ecspi3.RDY
  uart3.TX
  uart3.RX
  uart3.CTS_B
  uart3.RTS_B
  spdif.EXT_CLK
  usb.OTG1_PWR
  usb.OTG1_OC
  anatop.OTG1_ID
  usb.OTG2_PWR
  usb.OTG2_OC
  anatop.OTG2_ID
  uart6.TX
  uart6.RX
  uart6.RTS_B
  uart6.CTS_B
  uart5.TX
  uart5.RX
  uart5.RTS_B
  uart5.CTS_B
  usdhc1.WP
  usdhc1.CD_B
  usdhc1.RESET_B
  usdhc1.VSELECT
- uart5.TX
  uart5.RX
  uart5.CTS_B
  uart5.RTS_B
  epdc.PWRCTRL[1]
  epdc.PWRCTRL[2]
  epdc.PWRCTRL[3]
  epdc.SDCE[4]
  epdc.SDCE[5]
  epdc.SDCE[6]
  epdc.SDCE[7]
  epdc.SDCE[8]
  epdc.SDCE[9]
  epdc.SDOED
  epdc.SDOEZ
  epdc.SDDO[8]
  epdc.SDDO[9]
  epdc.SDDO[10]
  epdc.SDDO[11]
  epdc.SDDO[12]
  epdc.SDDO[13]
  epdc.SDDO[14]
  epdc.SDDO[15]
  epdc.SDCLK
  epdc.SDLE
  epdc.SDOE
  epdc.SDCE[0]
  epdc.GDOE
  epdc.SDDO[0]
  epdc.SDDO[1]
  epdc.SDDO[2]
  epdc.SDDO[3]
  epdc.SDDO[4]
  epdc.SDDO[5]
  epdc.SDDO[6]
  epdc.SDDO[7]
  epdc.PWRIRQ
  epdc.PWRWAKE
  epdc.PWRCOM
  epdc.PWRSTAT
  epdc.PWRCTRL[0]
  epdc.BDR[0]
  epdc.SDSHR
  epdc.GDRL
  epdc.GDCLK
  epdc.GDSP
  epdc.BDR[1]
  epdc.VCOM[0]
  epdc.VCOM[1]
  epdc.SDCE[1]
  epdc.SDCE[2]
  epdc.SDCE[3]
  esai.TX3_RX2
  esai.TX2_RX3
  esai.TX4_RX1
  esai.TX1
  esai.TX_HF_CLK
  esai.RX_HF_CLK
  esai.RX_FS
  esai.RX_CLK
  esai.TX_FS
  esai.TX_CLK
  esai.TX5_RX0
  esai.TX0
- 100K PD
  100K PU
  100K PU
  100K PU
  100K PD
  100K PD
  100K PD
  Keeper
  Keeper
  Keeper
  Keeper
  Keeper
  Keeper
  Keeper
  Keeper
  Keeper
  Keeper
  100K PU
  47K PU
  100K PU
  47K PU
  47K PU
  47K PU
  Keeper
  Keeper
  Keeper
  Keeper
  Keeper
  Keeper
  Keeper
  Keeper
  Keeper
  Keeper
  Keeper
  Keeper
  Keeper
  Keeper
  Keeper
  Keeper
  Keeper
  Keeper
  Keeper
  Keeper
  Keeper
  Keeper
  Keeper
  Keeper
  Keeper
  Keeper
  Keeper
  Keeper
  Keeper
  Keeper
  Keeper
  Keeper
  Keeper
  Keeper
  Keeper
  Keeper
  Keeper
  Keeper
  Keeper
  Keeper
  Keeper
  Keeper
  Keeper
  Keeper
  Keeper
  Keeper
  Keeper
  Keeper
  Keeper
  Keeper
  Keeper
  Keeper
  Keeper
  Keeper
  Keeper
  Keeper
  Keeper
  Keeper
  Keeper
  Keeper
  Keeper
  Keeper
  Keeper
  Keeper
  Keeper
  Keeper
  Keeper
  Keeper
  Keeper
  Keeper
  Keeper
  Keeper
  Keeper
  Keeper
  Keeper
  Keeper
  Keeper
  Keeper
  Keeper
  Keeper
  Keeper
  Keeper
  Keeper
  Keeper
  Keeper
  Keeper
  Keeper
  Keeper
  Keeper
  Keeper
  Keeper
  Keeper
  Keeper
  Keeper
  Keeper
  Keeper
  Keeper
  Keeper
  Keeper
  Keeper
  Keeper
  Keeper
  Keeper
  Keeper
  Keeper
  Keeper

## Sheet P03 POWER TREE.SchDoc
size 594 x 420 mm
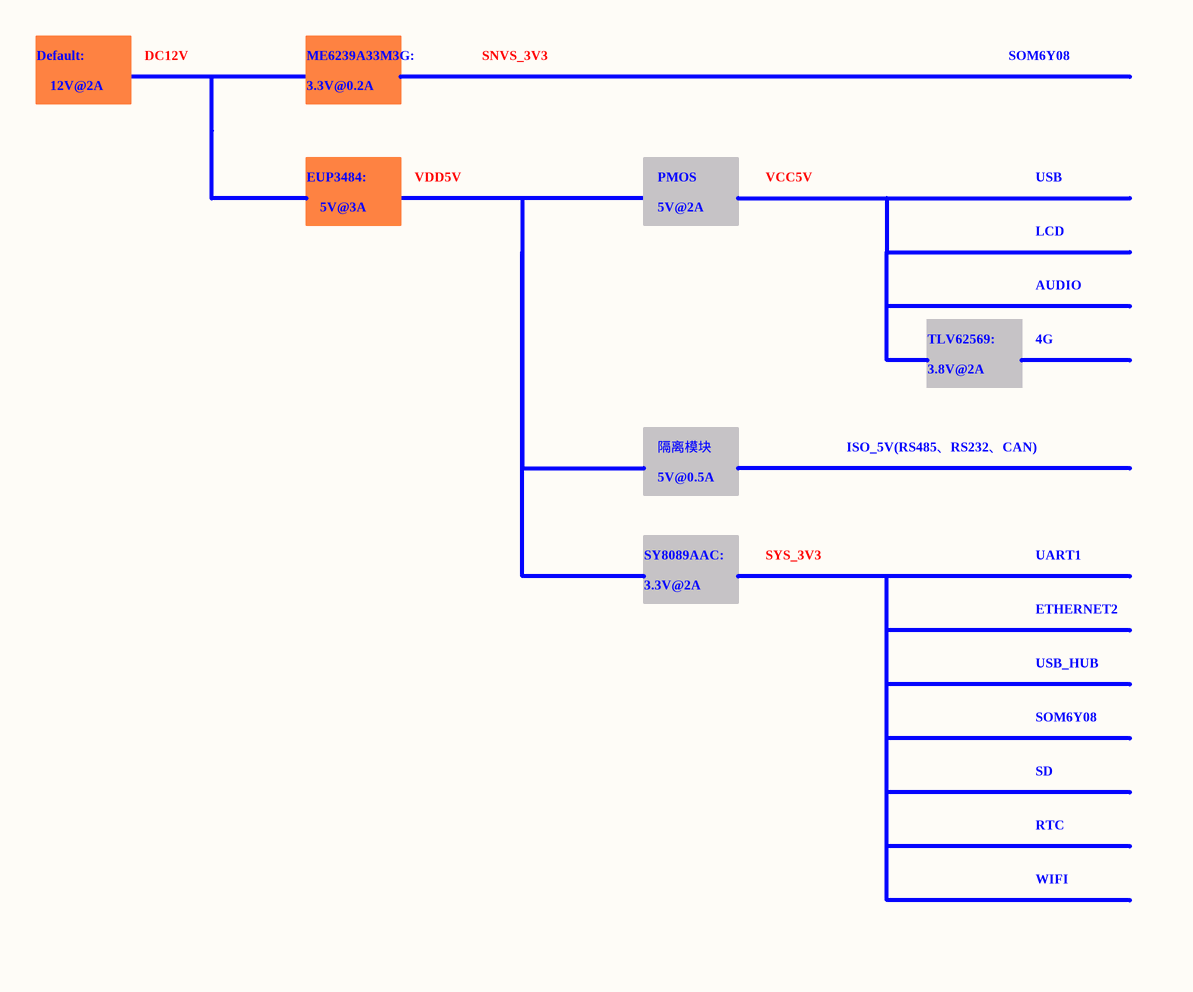
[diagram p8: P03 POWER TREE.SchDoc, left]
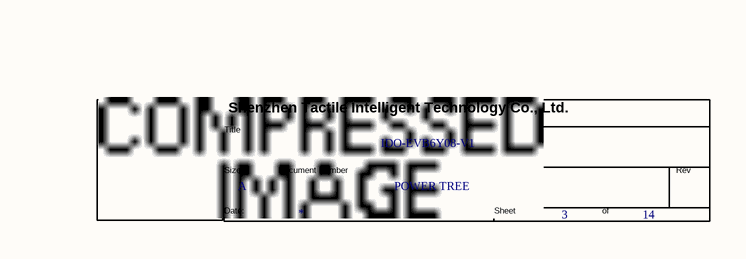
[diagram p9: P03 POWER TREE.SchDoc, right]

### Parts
(Parts that share a designator on the sheet are numbered #1, #2 ... from top to bottom, then left to right.)
*#3  Doc: POWER TREE  Title: IDO-EVB6Y08-V1  Page Size: A  Page Number: 3  Page Count: 14  (hidden comment: TitleBlock1)  (graphical)

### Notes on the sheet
- Default:
- 12V@2A
- DC12V
- 3.3V@0.2A
- ME6239A33M3G:
- SNVS_3V3
- SOM6Y08
- EUP3484:
- VDD5V
- PMOS
- VCC5V
- USB
- 5V@3A
- 5V@2A
- LCD
- AUDIO
- TLV62569:
- 3.8V@2A
- 4G
- 隔离模块
- ISO_5V(RS485、RS232、CAN)
- 5V@0.5A
- SY8089AAC:
- 3.3V@2A
- SYS_3V3
- UART1
- ETHERNET2
- USB_HUB
- SD
- RTC
- WIFI

## Sheet P04 BLOCK.SchDoc
size 594 x 420 mm
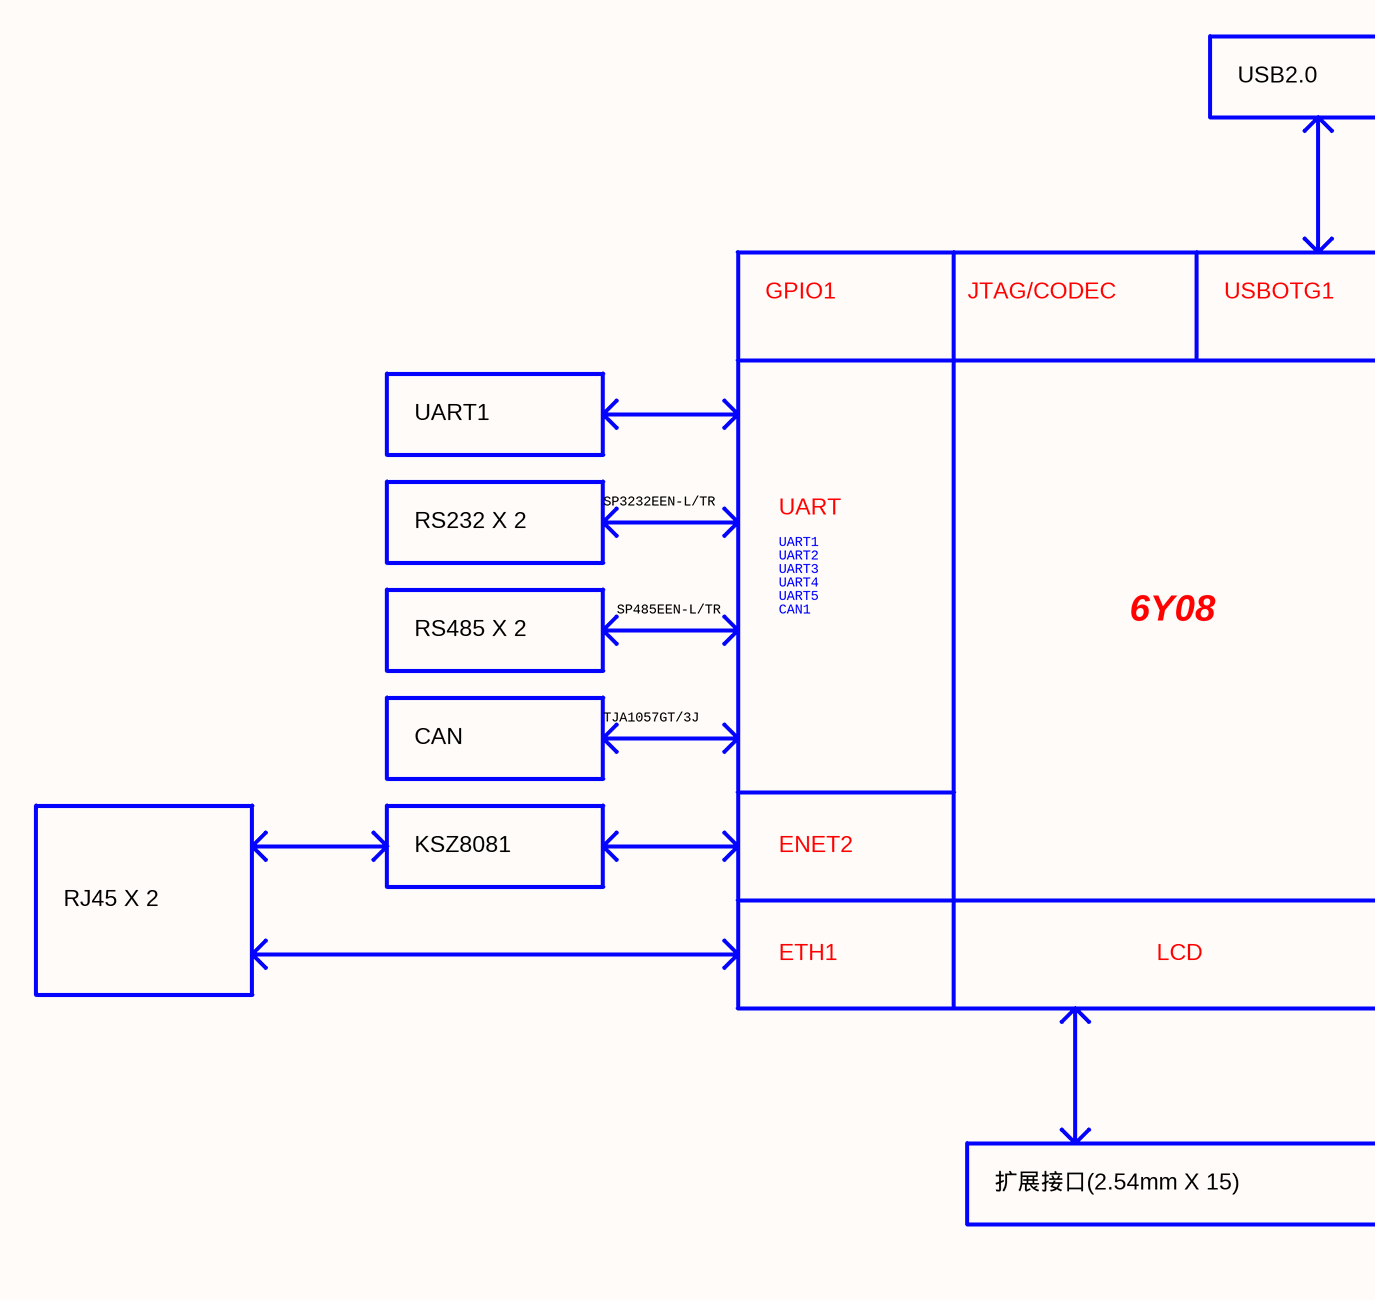
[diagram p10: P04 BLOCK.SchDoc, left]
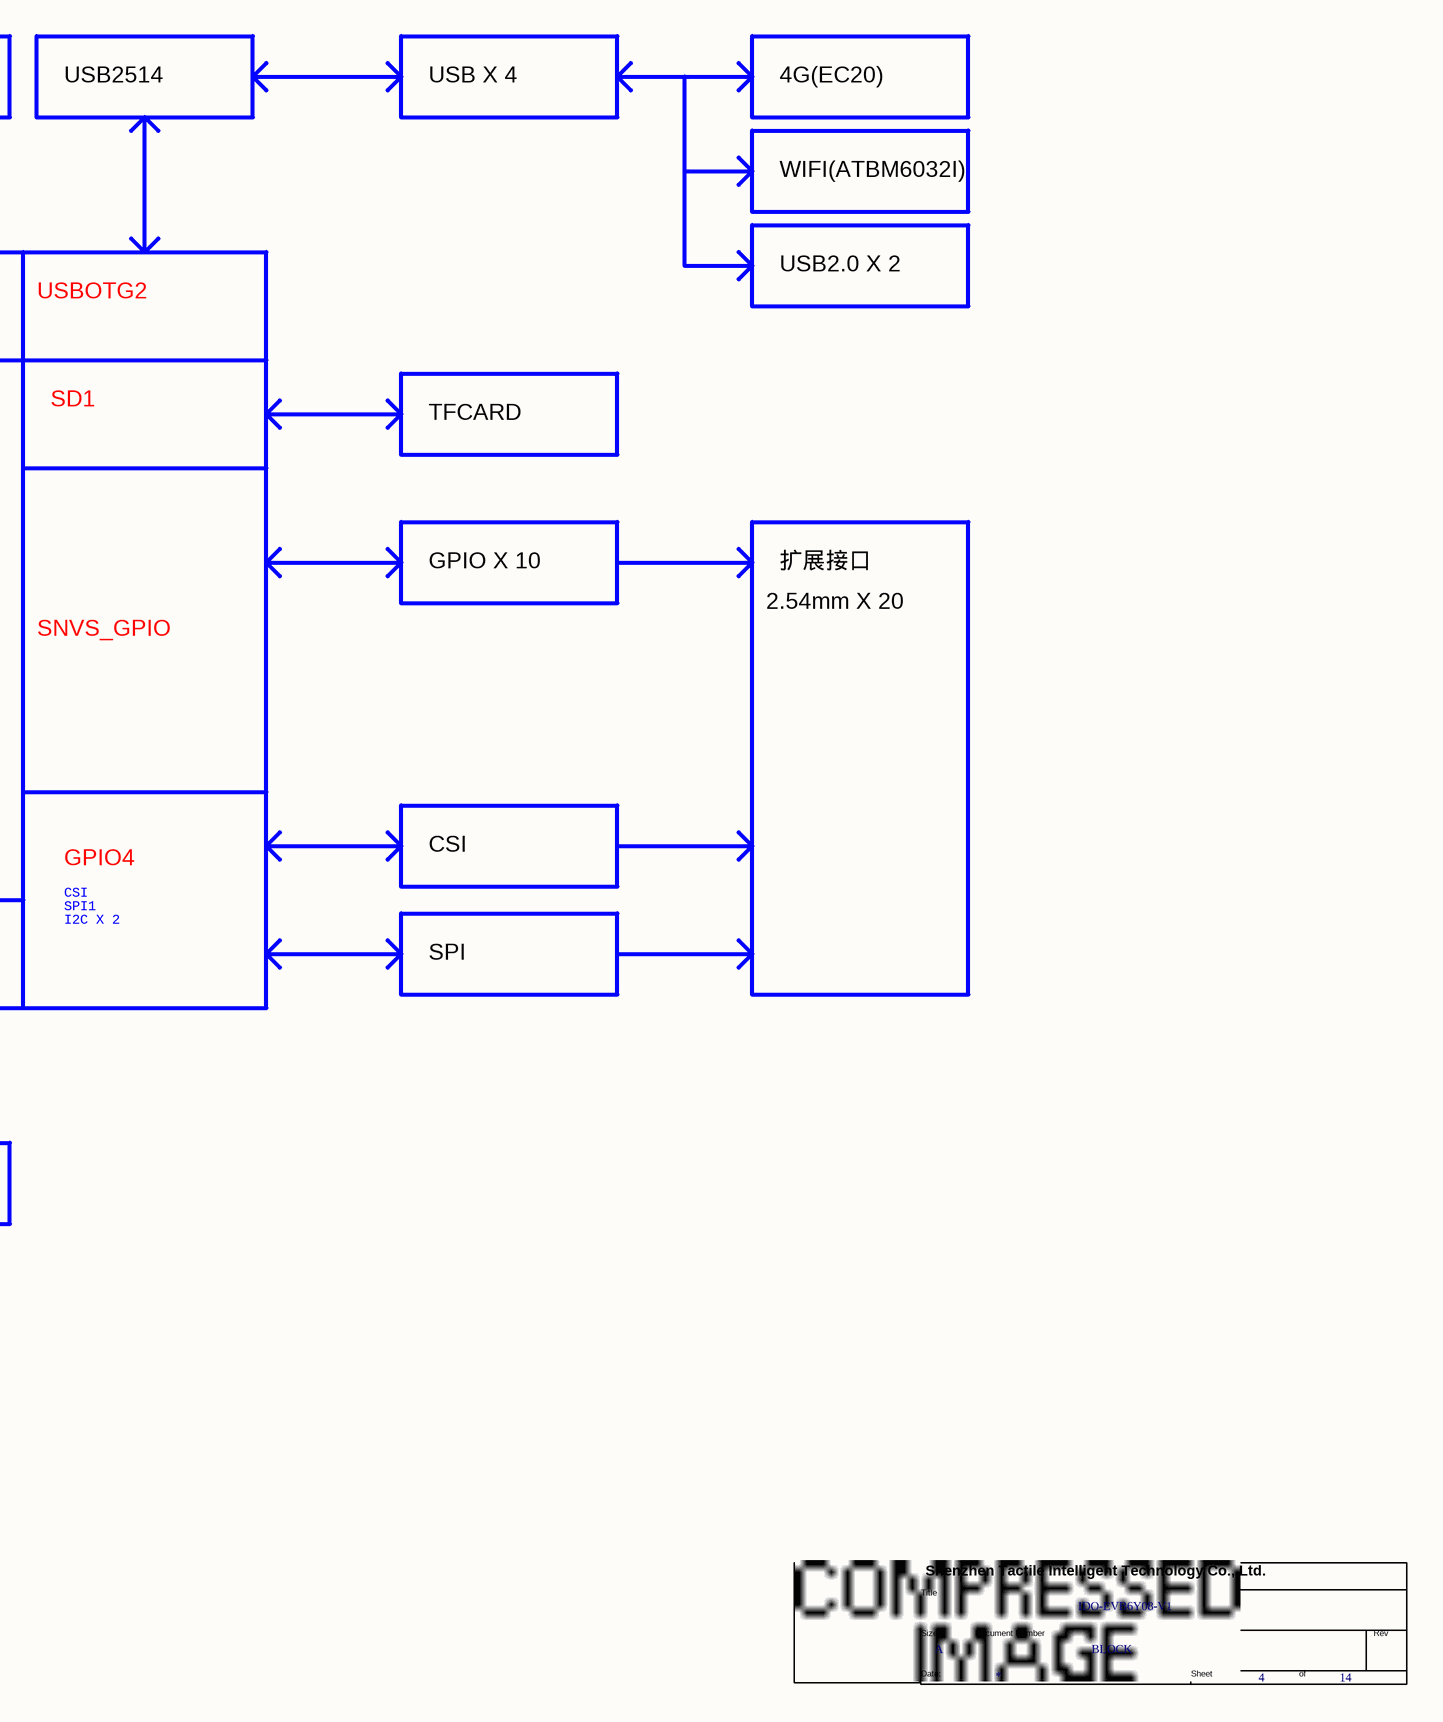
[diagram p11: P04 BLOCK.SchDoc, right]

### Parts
(Parts that share a designator on the sheet are numbered #1, #2 ... from top to bottom, then left to right.)
*#4  Doc: BLOCK  Title: IDO-EVB6Y08-V1  Page Size: A  Page Number: 4  Page Count: 14  (hidden comment: TitleBlock1)  (graphical)

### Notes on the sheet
- USB2.0
- USB2514
- USB X 4
- 4G(EC20)
- WIFI(ATBM6032I)
- GPIO1
- JTAG/CODEC
- USBOTG1
- USBOTG2
- USB2.0 X 2
- UART1
- SD1
- TFCARD
- SP3232EEN-L/TR
- RS232 X 2
- UART
- UART2
- UART3
- GPIO X 10
- 扩展接口
- RS485 X 2
- SP485EEN-L/TR
- UART4
- UART5
- CAN1
- 6Y08
- SNVS_GPIO
- 2.54mm X 20
- CAN
- TJA1057GT/3J
- RJ45 X 2
- KSZ8081
- ENET2
- GPIO4
- CSI
- SPI1
- ETH1
- LCD
- I2C X 2
- SPI
- 扩展接口(2.54mm X 15)

## Sheet P05 POWER_SUPPLY_LED.SchDoc
size 594 x 420 mm
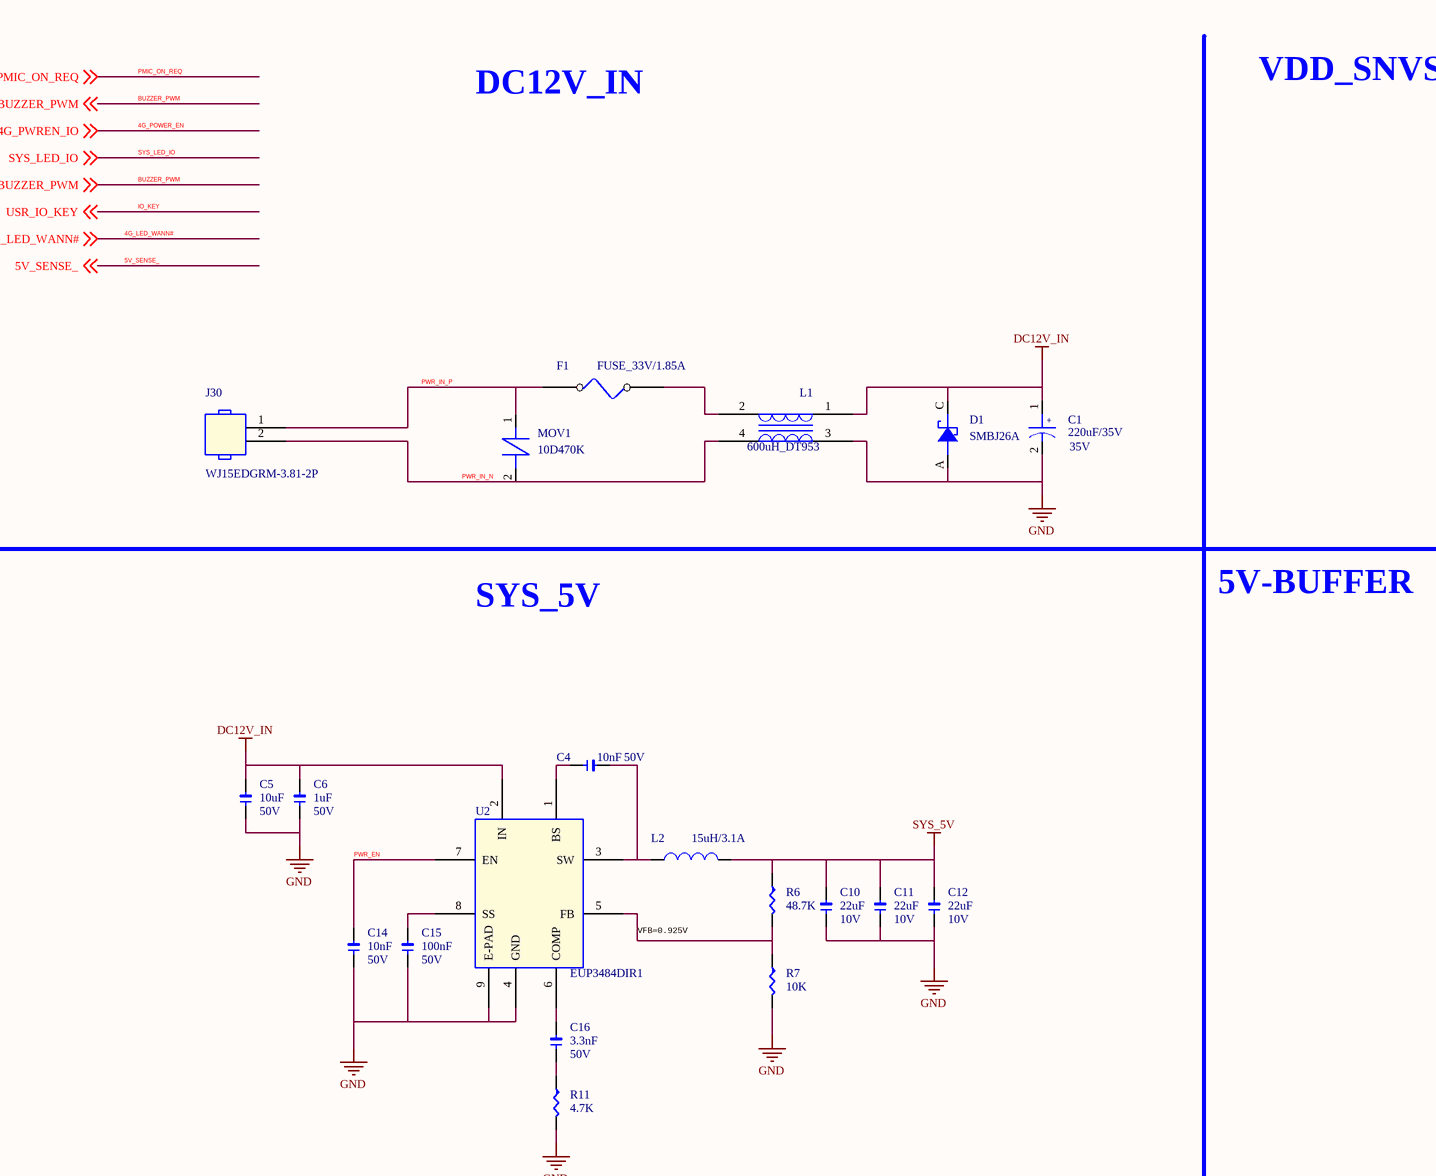
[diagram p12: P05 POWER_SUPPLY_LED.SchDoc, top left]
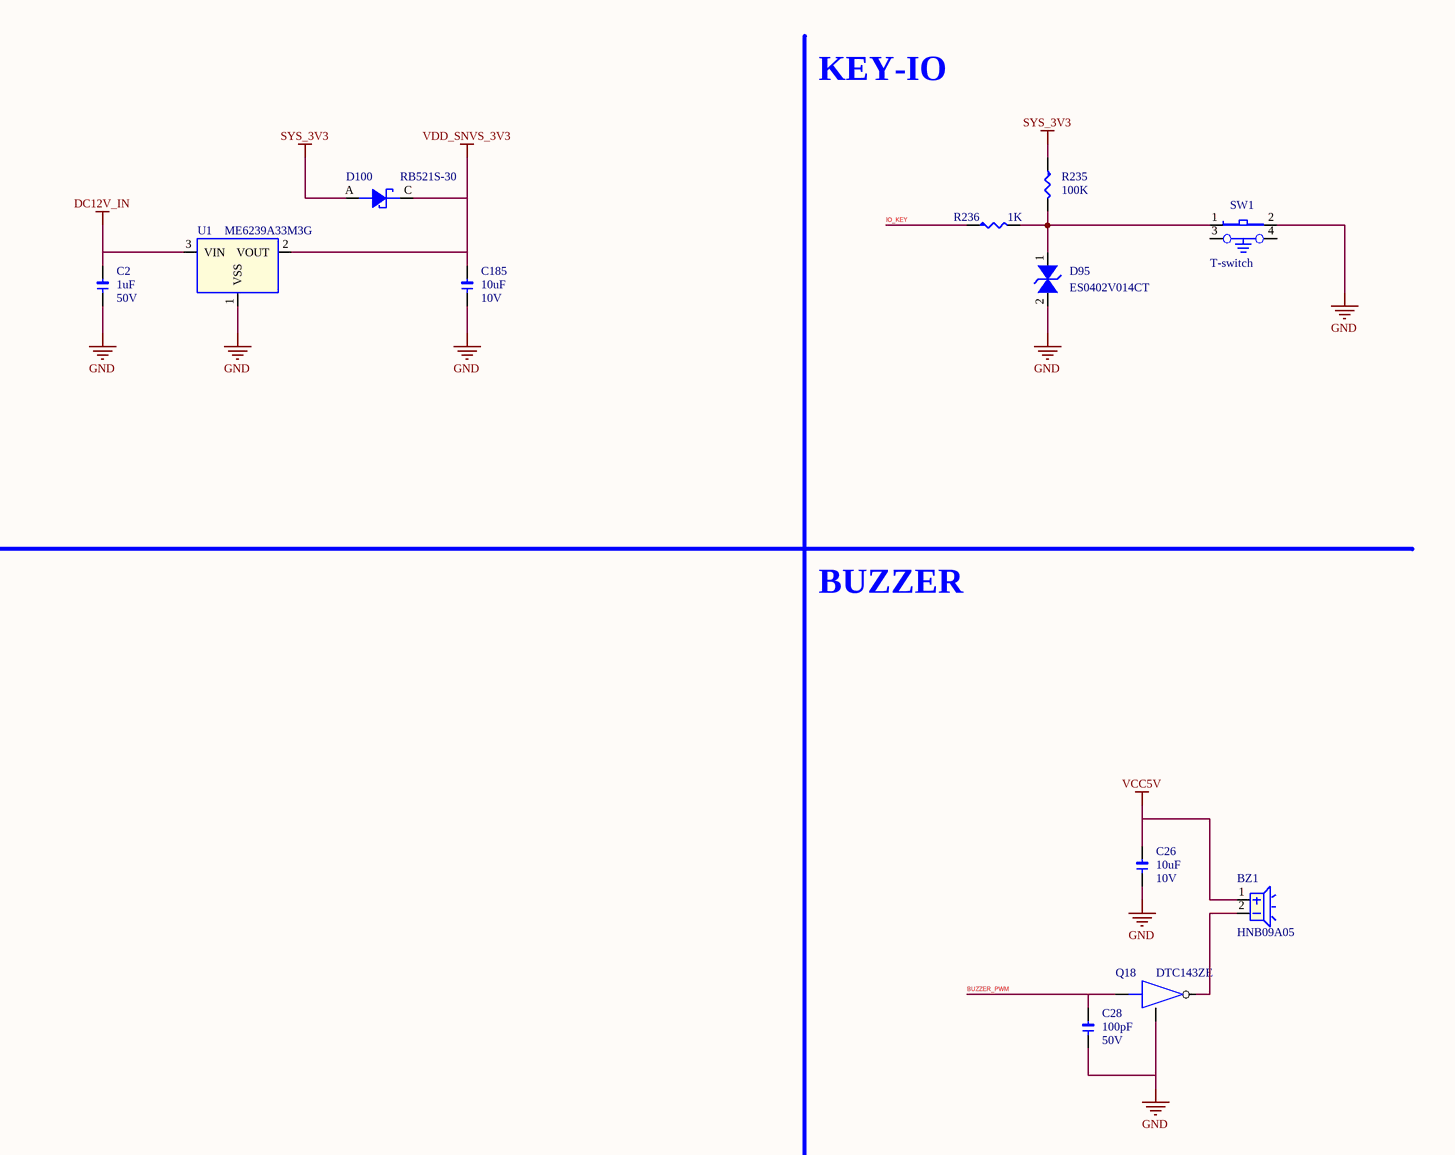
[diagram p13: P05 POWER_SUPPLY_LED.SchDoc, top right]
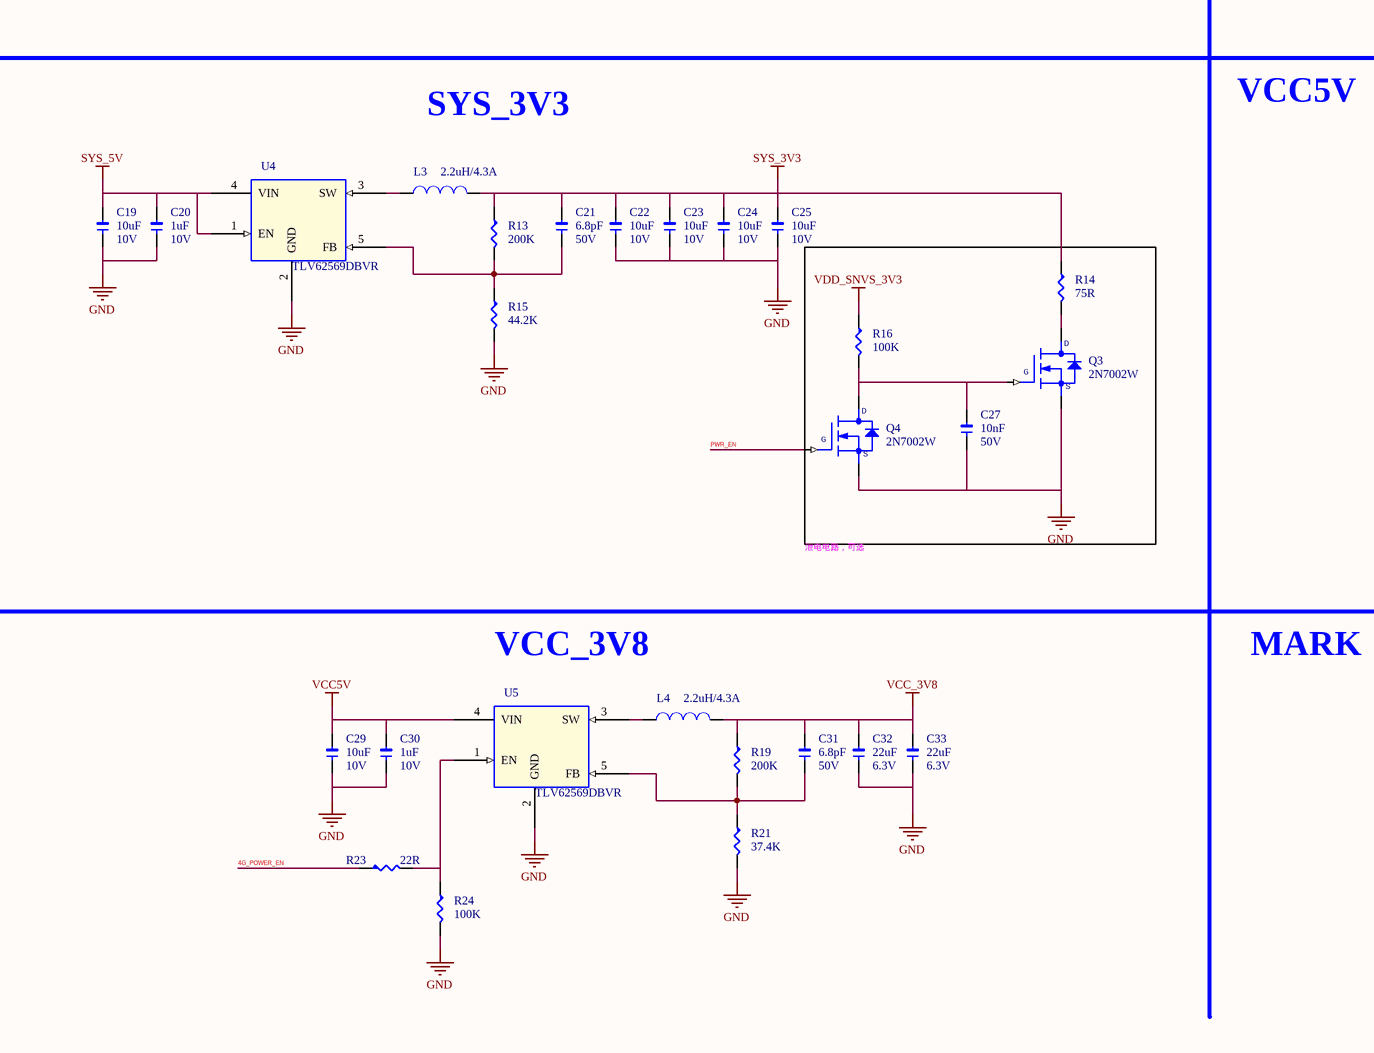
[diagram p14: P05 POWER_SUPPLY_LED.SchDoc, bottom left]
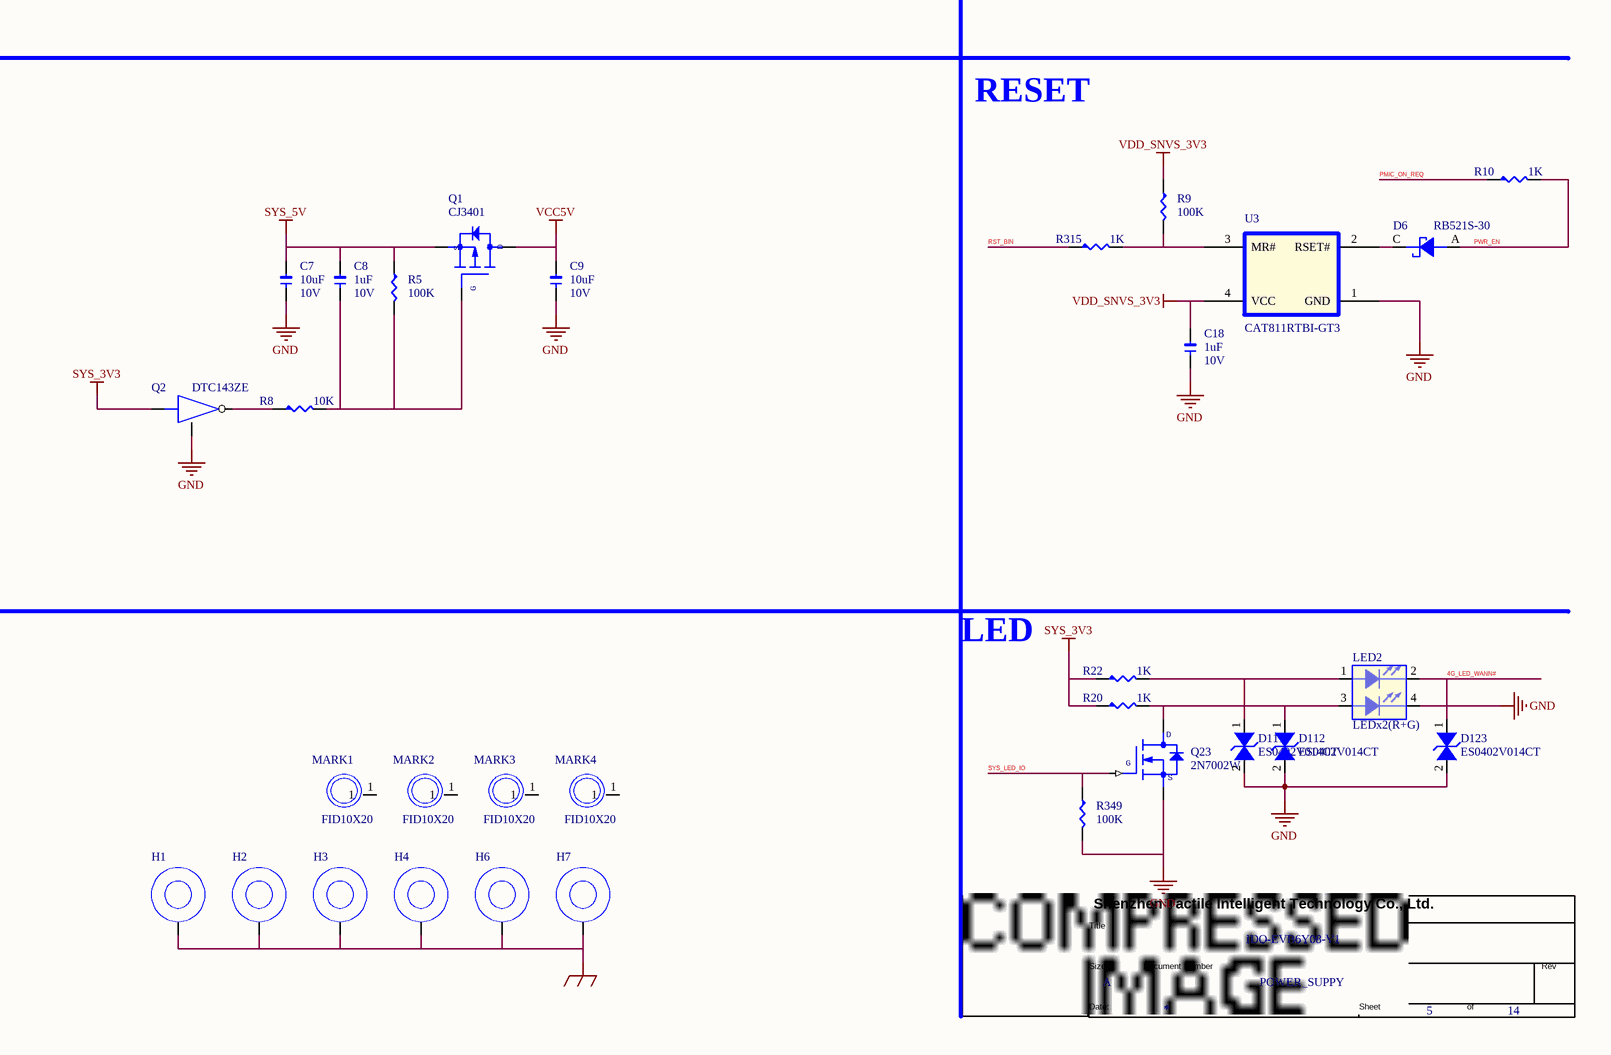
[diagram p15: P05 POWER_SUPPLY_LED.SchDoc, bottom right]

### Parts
(Parts that share a designator on the sheet are numbered #1, #2 ... from top to bottom, then left to right.)
*#5  Doc: POWER_SUPPY  Title: IDO-EVB6Y08-V1  Page Size: A  Page Number: 5  Page Count: 14  (hidden comment: TitleBlock1)  (graphical)
BZ1  HNB09A05  [buzzer_12_2-2p]
C1  220uF/35V  DSC2: 35V  [CAPAE830X1050]
C2  1uF  DSC2: 50V  [1206]
C4  10nF  DSC2: 50V  [1206]
C5  10uF  DSC2: 50V  [1206]
C6  1uF  DSC2: 50V  [1206]
C7  10uF  DSC2: 10V  [1206]
C8  1uF  DSC2: 10V  [1206]
C9  10uF  DSC2: 10V  [1206]
C10  22uF  DSC2: 10V  [1206]
C11  22uF  DSC2: 10V  [1206]
C12  22uF  DSC2: 10V  [1206]
C14  10nF  DSC2: 50V  [1206]
C15  100nF  DSC2: 50V  [1206]
C16  3.3nF  DSC2: 50V  [1206]
C18  1uF  DSC2: 10V  [1206]
C19  10uF  DSC2: 10V  [1206]
C20  1uF  DSC2: 10V  [1206]
C21  6.8pF  DSC2: 50V  [1206]
C22  10uF  DSC2: 10V  [1206]
C23  10uF  DSC2: 10V  [1206]
C24  10uF  DSC2: 10V  [1206]
C25  10uF  DSC2: 10V  [1206]
C26  10uF  DSC2: 10V  [1206]
C27  10nF  DSC2: 50V  [1206]
C28  100pF  DSC2: 50V  [1206]
C29  10uF  DSC2: 10V  [1206]
C30  1uF  DSC2: 10V  [1206]
C31  6.8pF  DSC2: 50V  [1206]
C32  22uF  DSC2: 6.3V  [1206]
C33  22uF  DSC2: 6.3V  [1206]
C185  10uF  DSC2: 10V  [1206]
D1  SMBJ26A  [SMB_DO-214AA]
D6  RB521S-30  [SOD523]
D95  ES0402V014CT  [V0402]
D100  RB521S-30  [SOD523]
D111  ES0402V014CT  [V0402]
D112  ES0402V014CT  [V0402]
D123  ES0402V014CT  [V0402]
F1  FUSE_33V/1.85A  [SMD2920]
H1  HOLE  [mtg370_600]  (value not drawn)
H2  HOLE  [mtg370_600]  (value not drawn)
H3  HOLE  [mtg370_600]  (value not drawn)
H4  HOLE  [mtg370_600]  (value not drawn)
H6  HOLE  [mtg370_600]  (value not drawn)
H7  HOLE  [mtg370_600]  (value not drawn)
J30  WJ15EDGRM-3.81-2P  [WJ15EDGRM-381T-2P]
L1  600uH_DT953  [CMLP-DT953]
L2  15uH/3.1A  [LM73x66]
L3  2.2uH/4.3A  [L4040]
L4  2.2uH/4.3A  [L4040]
LED2  LEDx2(R+G)  [LED_P254_2X2DIP]
MARK1  FID10X20  [FID10X20]
MARK2  FID10X20  [FID10X20]
MARK3  FID10X20  [FID10X20]
MARK4  FID10X20  [FID10X20]
MOV1  10D470K  [10D-SIP2-750]
Q1  CJ3401  [SOT23]
Q2  DTC143ZE  [SOT523]
Q3  2N7002W  [SOT323]
Q4  2N7002W  [SOT323]
Q18  DTC143ZE  [SOT523]
Q23  2N7002W  [SOT323]
R5  100K  [R0402L]
R6  48.7K  [R0402l]
R7  10K  [R0402L]
R8  10K  [R0402L]
R9  100K  [R0402L]
R10  1K  [R0402L]
R11  4.7K  [R0402L]
R13  200K  [R0402L]
R14  75R  [R0402L]
R15  44.2K  [R0402L]
R16  100K  [R0402L]
R19  200K  [R0402L]
R20  1K  [R0402L]
R21  37.4K  [R0402L]
R22  1K  [R0402L]
R23  22R  [R0402L]
R24  100K  [R0402L]
R235  100K  [R0402L]
R236  1K  [R0402L]
R315  1K  [R0402L]
R349  100K  [R0402L]
SW1  T-switch  [PB-SIDE-S-3x6]
U1  ME6239A33M3G  [SOT23]
U2  EUP3484DIR1  [ESOP8-P127-390X490]
U3  CAT811RTBI-GT3  [SOT143]
U4  TLV62569DBVR  [SOT23-5]
U5  TLV62569DBVR  [SOT23-5]

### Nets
DC12V_IN: C1.1 C2.2 C5.2 C6.2 D1.C L1.1 U1.3(VIN) U2.2(IN)
GND: C1.2 C2.1 C5.1 C6.1 C7.1 C9.1 C10.1 C11.1 C12.1 C14.1 C15.1 C18.1 C19.1 C20.1 C22.1 C23.1 C24.1 C25.1 C26.1 C27.1 C28.1 C29.1 C30.1 C32.1 C33.1 C185.1 D1.A D95.2(I/O1) D111.2(I/O1) D112.2(I/O1) D123.2(I/O1) L1.3 LED2.4 Q2.2 Q3.2(SOURCE) Q4.2(SOURCE) Q18.2 Q23.2(SOURCE) R7.2 R11.2 R15.2 R21.2 R24.2 R349.2 SW1.2 U1.1(VSS) U2.4(GND) U2.9(E-PAD) U3.1(GND) U4.2(GND) U5.2(GND)
GND_EARTH: H1.1 H2.1 H3.1 H4.1 H6.1 H7.1
SYS_3V3: C21.2 C22.2 C23.2 C24.2 C25.2 D100.A L3.2 Q2.1 R13.1 R14.1 R20.1 R22.1 R235.1
SYS_5V: C7.2 C8.2 C10.2 C11.2 C12.2 C19.2 C20.2 L2.2 Q1.2(SOURCE) R5.1 R6.1 U4.1(EN) U4.4(VIN)
VCC5V: BZ1.1(+) C9.2 C26.2 C29.2 C30.2 Q1.3(DRAIN) U5.4(VIN)
VCC_3V8: C31.2 C32.2 C33.2 L4.2 R19.1
VDD_SNVS_3V3: C18.2 C185.2 D100.C R9.1 R16.1 U1.2(VOUT) U3.4(VCC)
4G_LED_WANN#: D123.1(I/O2) LED2.2 ; off-sheet 4G_LED_WANN#
4G_POWER_EN: R23.1 ; off-sheet 4G_PWREN_IO  [also labelled 4G_PWREN_IO]
BUZZER_PWM: C28.2 Q18.1 ; off-sheet BUZZER_PWM
IO_KEY: R236.1 ; off-sheet USR_IO_KEY  [also labelled USR_IO_KEY]
PMIC_ON_REQ: R10.1 ; off-sheet PMIC_ON_REQ
PWR_EN: C14.2 D6.A Q4.1(GATE) R10.2 U2.7(EN)
PWR_IN_N: J30.2 L1.4 MOV1.2(K)
PWR_IN_P: F1.1 J30.1 MOV1.1(A)
RST_BIN: R315.1
SYS_LED_IO: Q23.1(GATE) R349.1 ; off-sheet SYS_LED_IO  [project net SNVS_TAMPER7]
NetBZ1_2: BZ1.2(-) Q18.3
NetC4_1: C4.1 U2.1(BS)
NetC4_2: C4.2 L2.1 U2.3(SW)
NetC8_1: C8.1 Q1.1(GATE) R5.2 R8.2
NetC15_2: C15.2 U2.8(SS)
NetC16_1: C16.1 R11.1
NetC16_2: C16.2 U2.6(COMP)
NetC21_1: C21.1 R13.2 R15.1 U4.5(FB)
NetC27_2: C27.2 Q3.1(GATE) Q4.3(DRAIN) R16.2
NetC31_1: C31.1 R19.2 R21.1 U5.5(FB)
NetD6_C: D6.C U3.2(RSET#)
NetD95_1: D95.1(I/O2) R235.2 R236.2 SW1.1
NetD111_1: D111.1(I/O2) LED2.1 R22.2
NetD112_1: D112.1(I/O2) LED2.3 Q23.3(DRAIN) R20.2
NetF1_2: F1.2 L1.2
NetL3_1: L3.1 U4.3(SW)
NetL4_1: L4.1 U5.3(SW)
NetQ2_3: Q2.3 R8.1
NetQ3_3: Q3.3(DRAIN) R14.2
NetR6_2: R6.2 R7.1 U2.5(FB)
NetR9_2: R9.2 R315.2 U3.3(MR#)
NetR23_2: R23.2 R24.1 U5.1(EN)

Not connected (* = marked no-connect by the designer): MARK1 1; MARK2 1; MARK3 1; MARK4 1; SW1 3 4

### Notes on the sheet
- DC12V_IN
- VDD_SNVS_3V3
- KEY-IO
- SYS_5V
- 5V-BUFFER
- BUZZER
- VFB=0.925V
- VCC5V
- RESET
- SYS_3V3
- 泄电电路，可选
- LED
- VCC_3V8
- MARK

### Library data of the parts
BZ1 = BZ-HNB09A05: Part Name: 蜂鸣器; Part Number: C210102740001; DSC1: 9*5.5mm，直插; DSC2: 有源蜂鸣器,5V; ID: 1
C1 = C-AL-SMD: Manufacture: 先科¦立隆¦三莹; Part Name: 贴片铝电容; Part Number: C020302140013; ID: 13; DSC8: VZH221M1VTR-0810(立隆); DSC7: FZ1V221M-CRF10(ST); DSC6: SMD,8x10.5mm; DSC5: -55~105 ℃; DSC4: 5000H; DSC3: 低阻抗长寿命; DSC1: ±20%
C2 C6 = C-0603: Manufacture: 三星¦国巨¦村田; Part Name: 贴片电容; Part Number: C020102120069; ID: 69; DSC3: X5R; DSC1: ±10%; ERP Number: 1010200142; PCB Footprint: C0603L
C4 C14 C27 = C-0402: Manufacture: 三星¦国巨¦村田; Part Name: 贴片电容; Part Number: C020102120057; ID: 57; DSC3: X7R; DSC1: ±10%; ERP Number: 1010200077; PCB Footprint: C0402L
C5 = C-1206: Manufacture: 三星¦国巨¦村田; Part Name: 贴片电容; Part Number: C020103263826; ID: 79; DSC3: X5R; DSC1: ±10%; PCB Footprint: C1206L
C7 C9 C19 = C-0603: Part Number: C020102120071; Part Name: 贴片电容; Manufacture: 三星¦国巨¦村田; ERP Number: 1010200076; DSC1: ±20%; DSC3: X5R; ID: 71; PCB Footprint: C0603L
C8 C18 C20 = C-0402: Part Number: C020102120064; Part Name: 贴片电容; Manufacture: 三星¦国巨¦村田; ERP Number: 1010200054; DSC1: ±10%; DSC3: X5R; ID: 64; PCB Footprint: C0402L
C10-C12 = C-0805: Manufacture: 三星¦国巨¦村田; Part Name: 贴片电容; Part Number: C020102120075; ID: 75; DSC3: X5R; DSC1: ±20%; PCB Footprint: C0805L
C15 = C-0402: Manufacture: 三星¦国巨¦村田; Part Name: 贴片电容; Part Number: C020102120061; ID: 61; DSC3: X7R; DSC1: ±10%; ERP Number: 1010200128; PCB Footprint: C0402L
C16 = C-0402: Manufacture: 三星¦国巨¦村田; Part Name: 贴片电容; Part Number: C020104013836; ID: 81; DSC3: X7R; DSC1: ±10%; PCB Footprint: C0402L
C21 C31 = C-0402: Manufacture: 三星¦国巨¦村田; Part Name: 贴片电容; Part Number: C020102120018; ID: 18; DSC3: C0G; DSC1: ±0.25PF; ERP Number: 1010200056; PCB Footprint: C0402L
C22-C26 C29 C185 = C-0603: Manufacture: 三星¦国巨¦村田; Part Name: 贴片电容; Part Number: C020102120071; ID: 71; DSC3: X5R; DSC1: ±20%; ERP Number: 1010200076; PCB Footprint: C0603L
C28 = C-0402: Part Number: C020102120040; Part Name: 贴片电容; Manufacture: 三星¦国巨¦村田; ERP Number: 1010200152; DSC1: ±5%; DSC3: C0G; ID: 40; PCB Footprint: C0402L
C30 = C-0402: Manufacture: 三星¦国巨¦村田; Part Name: 贴片电容; Part Number: C020102120064; ID: 64; DSC3: X5R; DSC1: ±10%; ERP Number: 1010200054; PCB Footprint: C0402L
C32 C33 = C-0603: Part Number: C020102120072; Part Name: 贴片电容; Manufacture: 三星¦国巨¦村田; ERP Number: 1010200133; DSC1: ±20%; DSC3: X5R; ID: 72; PCB Footprint: C0603L
D1 = DI-XI-S: Part Number: C040602260007; Part Name: TVS; Manufacture: MDD¦伯恩半导体; CLASS: IC; ERP Number: 1010800043; DSC1: 单向; DSC2: Vrwm=26V; DSC3: VBR=28.9V; DSC4: Vc=42.1V; DSC5: Ipp=14.2A; DSC6: Ppp=800W; ID: 7
D6 D100 = DI-XI-S: Part Number: C040202220015; Part Name: 肖特基二级管; Manufacture: 长电; CLASS: IC; ERP Number: 1010800004; DSC1: VR=30V; DSC2: IF=200mA; DSC3: VF=100mV/10mA; DSC4: IR=30uA; ID: 15; Solder: 量产
D95 D111 D112 D123 = DI-ESD: ESD 0402; Part Number: C040502250002; Manufacture P/N: MLVG04021R0UV18; Manufacturer: INPAQ; Manufacture: AEM; PN Type: Varistor; ID: 2; DSC5: Cj=0.25pF; DSC4: Vc=30V; DSC3: Vbr=300V; DSC2: Vdc=14V; DSC1: 双向; ERP Number: 1010800023
F1 = FUSE-SMD2920: Part Number: C160102670010; Part Name: 自恢复保险丝; Manufacture: RUILON; DSC1: 33V; DSC2: 1.85A; DSC3: SMD2920P185TF; ID: 10
J30 = J-PCB-Con-2P: Part Name: PCB插拔式接线端子; Part Number: J040202890080; ID: 42; DSC5: WJ15EDGRM-3.81-2P(康奈克斯); DSC4: 绿色 带法兰; DSC3: 通孔弯针; DSC2: 2P; DSC1: 3.81mm
L1 = L-600uH_DT953: Part Number: C060402360008; Part Name: 电源共模电感; ID: 8; DSC6: 9*5*3mm,0.5线 四脚插件; DSC3: 2A; DSC1: 600uH
L2 = L-IND: Manufacture: 顺翔诺¦长江微电); Part Number: C060202340041; Part Name: 功率电感; ID: 41; DSC7: FXL0630-150-M(长江微电); DSC6: SMMS0630-150M(顺翔诺); DSC5: 7.3*6.6*3.0mm; DSC4: 112mΩ; DSC3: Irms=3.1A; DSC2: Isat=4.6A; DSC1: ±20%
L3 L4 = L-IND: Part Name: 功率电感; Part Number: C060202340020; Manufacture: 顺络; ERP Number: 1010200404; DSC1: ±20%; DSC2: Isat=6.1A; DSC3: Irms=4.3A; DSC4: 48mΩ; DSC5: 4.0*4.0*2.0mm; DSC6: WPN4020H2R2MT(顺络); ID: 20
LED2 = D-LED-DIP-2: Part Number: C140202660018; Part Name: LED; DSC1: 双孔座2位黑色方形灯柱 90度弯脚 左正右负 上红下绿; ID: 22
MARK1-MARK4 = MTG240_600_NPH_0: DSC2: 孔径2.4mm; DSC1: 禁止布线层直径=6mm; Type Name: 无铜固定孔; ID: 11
MOV1 = MOV-10D470K: Part Name: 压敏电阻; Part Number: C010502110001; Manufacture: HEL（鸿志）; ID: 1; ERP Number: 1010200264; DSC1: 浪涌电流=500A
Q1 = P-MOS: Part Number: C030202190001; Manufacture: 长电; ERP Number: 1010800001; DSC1: Vds=-30V; DSC2: Id=-4.2A; DSC3: Vgs(th)=1.3V; DSC4: Vgs=±12V; DSC5: pd=350mW; ID: 1
Q2 Q18 = S-NPN: Part Number: C030302200002; Part Name: 数字三极管; Manufacture: 长电; ERP Number: 1010800049; DSC1: NPN; DSC2: Ic=100mA; DSC3: Vce=50V; DSC4: 150mW; ID: 2
Q3 Q4 Q23 = N-MOS: Manufacture: 长电; Part Number: C030202190006; ID: 6; DSC5: pd=200mW; DSC4: Vgs=±20V; DSC3: Vgs(th)=2.5V; DSC2: Id=115mA; DSC1: Vds=60V; ERP Number: 1010800035
R5 R235 = R-0402: Part Name: 贴片电阻; Part Number: C011002080976; ERP Number: 1010200137; DSC1: ±1%; DSC2: 1/16W; ID: 976
R6 = R-0402: Part Name: 贴片电阻; Part Number: C011002080937; DSC1: ±1%; DSC2: 1/16W; ID: 937
R7 = R-0402: Part Name: 贴片电阻; Part Number: C011002080856; ERP Number: 1010200140; DSC1: ±1%; DSC2: 1/16W; ID: 856
R8 = R-0402: Part Number: C011002080856; Part Name: 贴片电阻; ID: 856; DSC2: 1/16W; DSC1: ±1%; ERP Number: 1010200140
R9 R16 R24 R349 = R-0402: Part Number: C011002080976; Part Name: 贴片电阻; ID: 976; DSC2: 1/16W; DSC1: ±1%; ERP Number: 1010200137
R10 R22 = R-0402: Part Number: C011002080742; Part Name: 贴片电阻; ID: 742; DSC2: 1/16W; DSC1: ±1%; ERP Number: 1010200113
R11 = R-0402: Part Number: C011002080818; Part Name: 贴片电阻; ID: 818; DSC2: 1/16W; DSC1: ±1%; ERP Number: 1010200445
R13 R19 = R-0402: Part Name: 贴片电阻; Part Number: C011002081009; ERP Number: 1010200139; DSC1: ±1%; DSC2: 1/16W; ID: 1,009
R14 = R-0402: Part Name: 贴片电阻; Part Number: C011002080616; ERP Number: 1010200187; DSC1: ±1%; DSC2: 1/16W; ID: 616
R15 = R-0402: Part Name: 贴片电阻; Part Number: C011002080931; ERP Number: 1010200256; DSC1: ±1%; DSC2: 1/16W; ID: 931
R20 R236 R315 = R-0402: Part Name: 贴片电阻; Part Number: C011002080742; ERP Number: 1010200113; DSC1: ±1%; DSC2: 1/16W; ID: 742
R21 = R-0402: Part Name: 贴片电阻; Part Number: C011002080922; ERP Number: 1010200444; DSC1: ±1%; DSC2: 1/16W; ID: 922
R23 = R-0402: Part Number: C011002080552; Part Name: 贴片电阻; ID: 552; DSC2: 1/16W; DSC1: ±1%
SW1 = SW-TS36CA: Part Name: 轻触开关; Part Number: C180102690002; ID: 2; DSC4: TSA365G00D-250(博瑞泰); DSC3: TS36CA-0.7(首韩); DSC2: SMD,3.5*7.7mm; DSC1: 轻触开关 侧键 贴片 带定位柱
U1 = U-ME6239A33M3G_1: Part Name: LDO; Part Number: C070102400020; Manufacture: 南京微盟; DSC1: Vi=5-30V; DSC2: Vo=3.3V; DSC3: Io=250mA; DSC5: Iq=1.5uA; ID: 20
U2 = U-EUP3484DIR1: Part Name: DCDC; Part Number: C070202410037; Manufacture: 台湾德信; ERP Number: 1010100145; DSC1: Vi=4.5-30V; DSC2: Vo=0.925-20V; DSC3: I=3A; DSC4: Vfb=0.925V; DSC5: 0.92; DSC6: 340KHz; DSC7: 同步降压; Solder: 量产; ID: 37
U3 = U-CAT811RTBI-GT3: Part Number: C110102550008; Part Name: 复位芯片; Manufacture: ON 安森美; DSC1: Detection Voltage: 2.63V,Active Low CMOS ouput 240mS, Iq=6uA,  Manual Reset Input; DSC2: SOT-143; DSC3: -40℃~+85℃; ID: 8
U4 U5 = U-TLV62569DBVR: Manufacture: TI; Part Number: C070202410003; Part Name: DCDC; ID: 3; Solder: 推荐; DSC7: 同步降压 轻载效率 低Iq; DSC6: 1.5MHz; DSC5: 0.95; DSC4: Vfb=0.6V; DSC3: Io=2A; DSC2: Vo=0.6-5.5V; DSC1: Vi=2.5-5.5V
